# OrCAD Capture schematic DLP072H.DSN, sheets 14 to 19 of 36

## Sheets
14 PAGE18- 2ND PMD POWER SUPPLIES: size A3
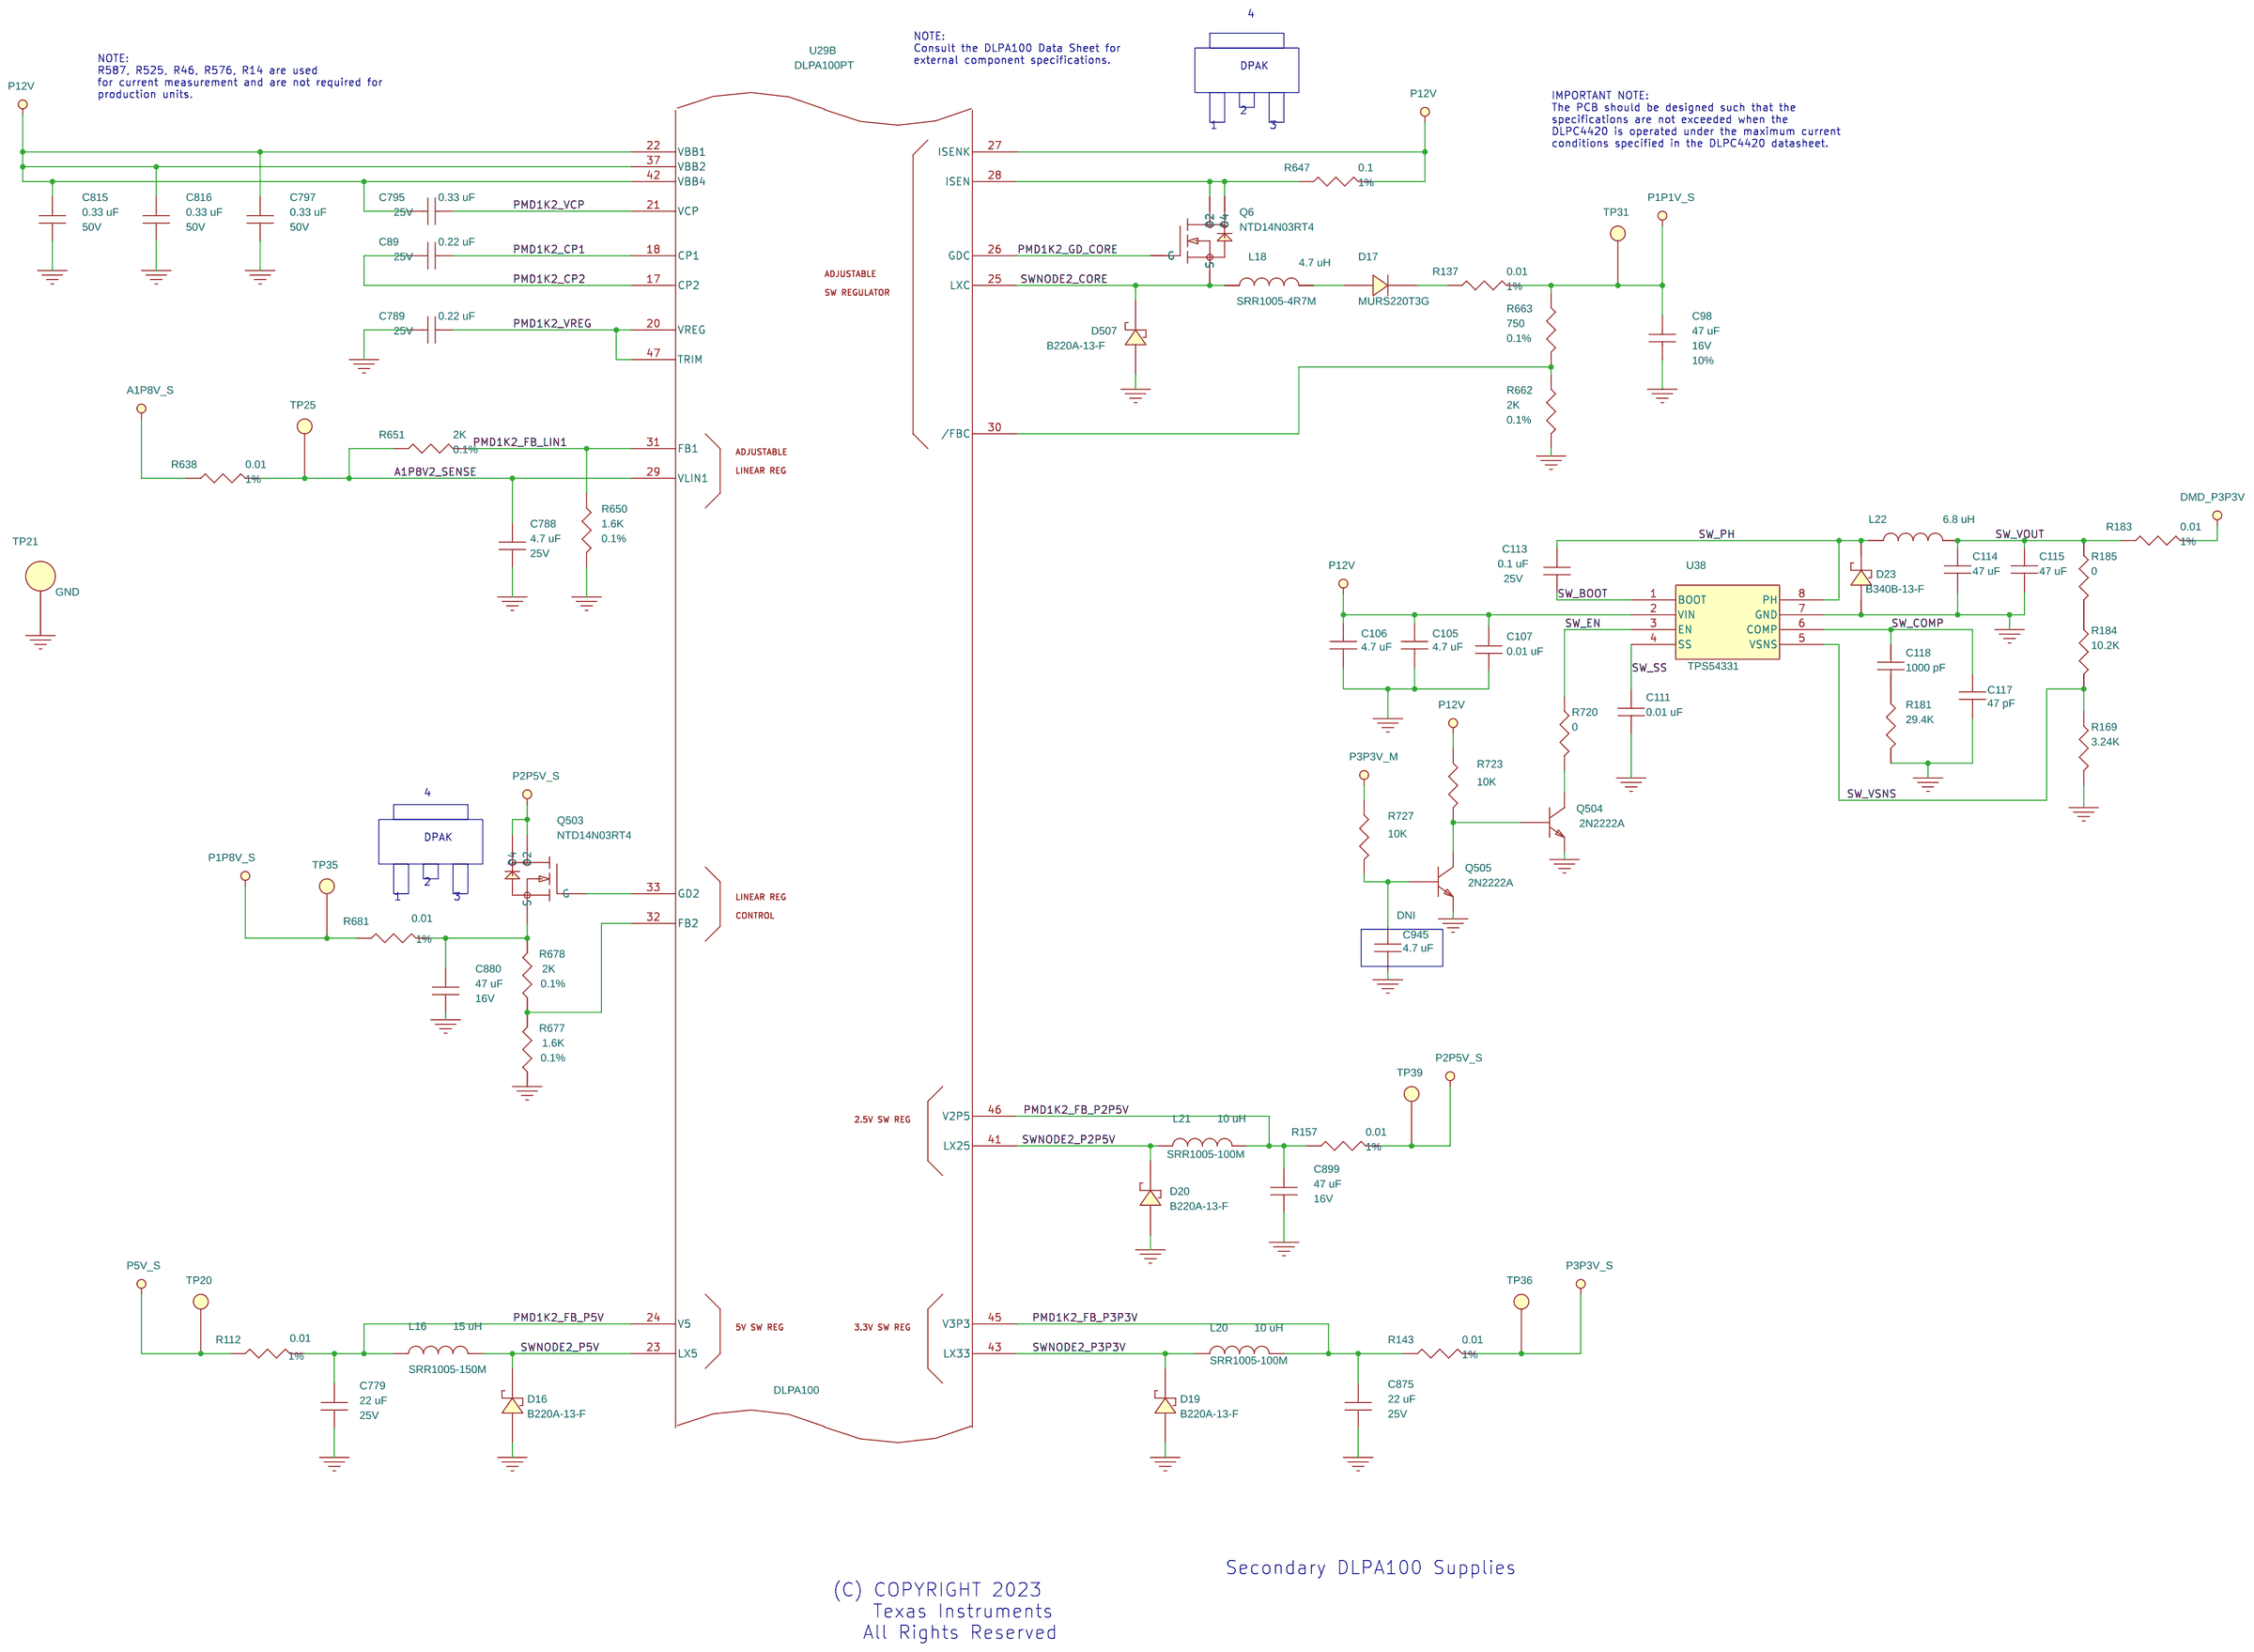
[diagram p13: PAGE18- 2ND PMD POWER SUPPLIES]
15 PAGE19 - COLOR WHEEL DRIVE: size A3
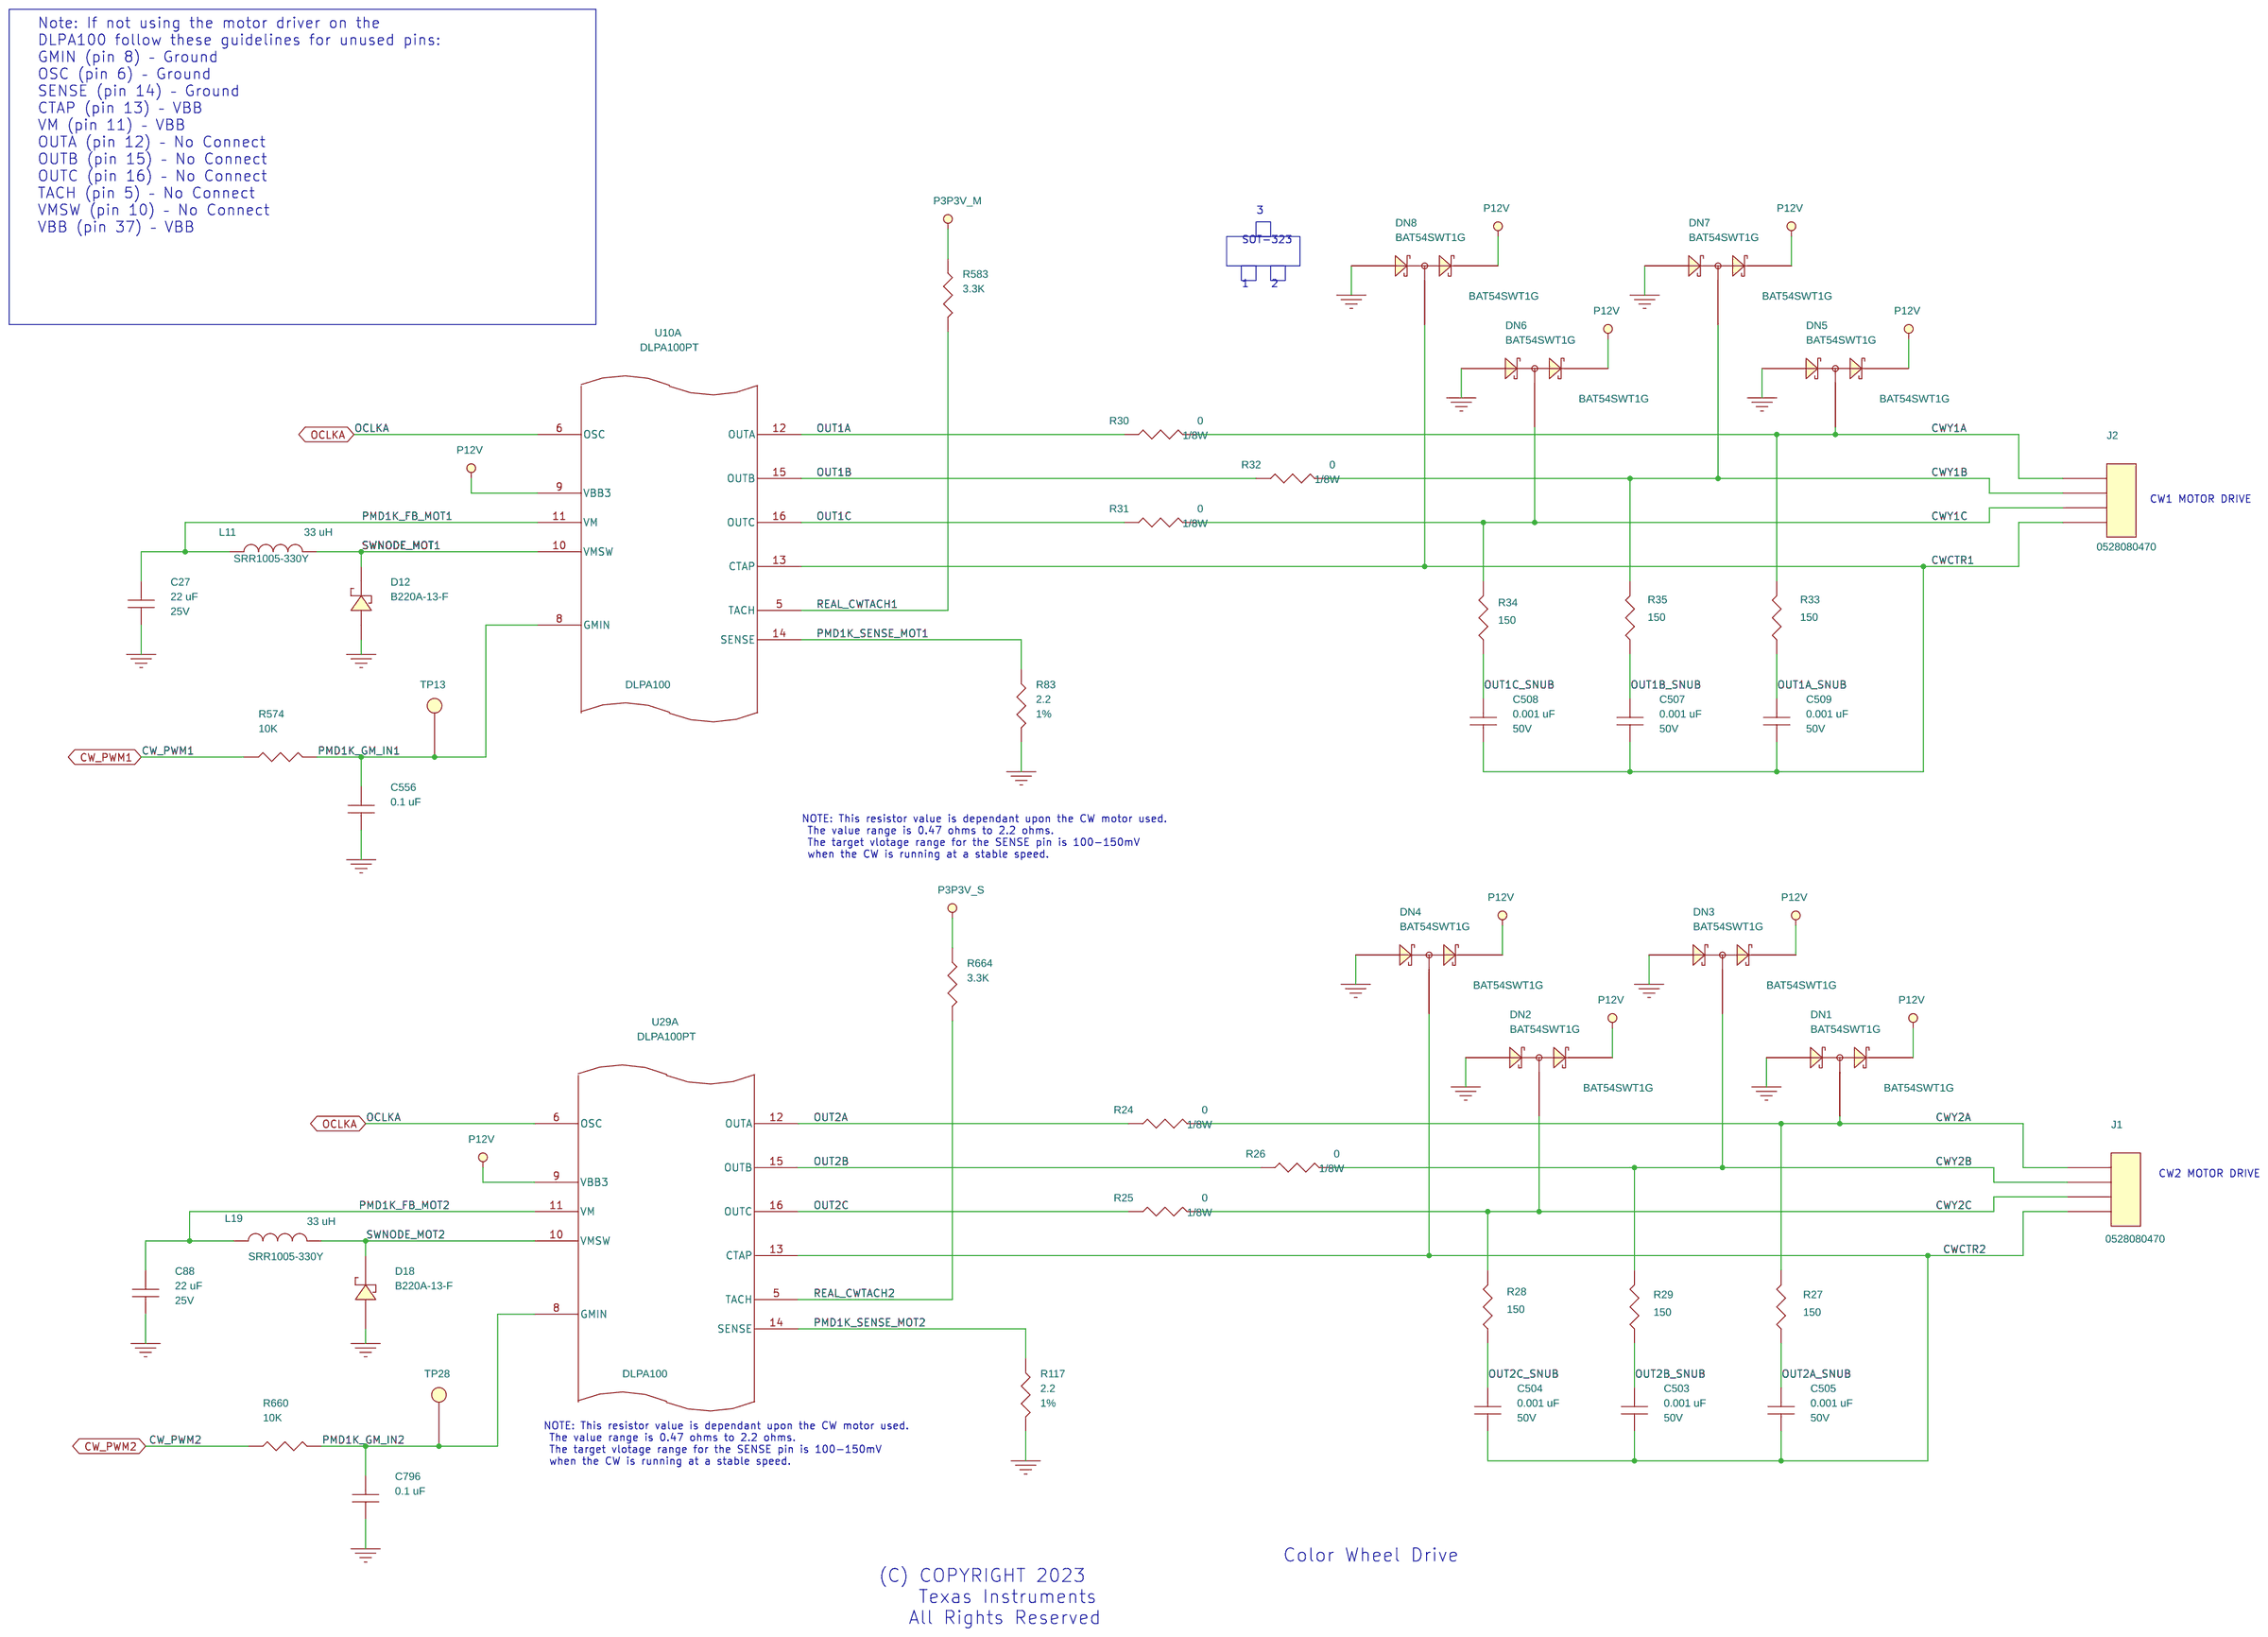
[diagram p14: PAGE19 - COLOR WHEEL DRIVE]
16 PAGE20 - FAN, CW INT & PERIPHLS: size A3
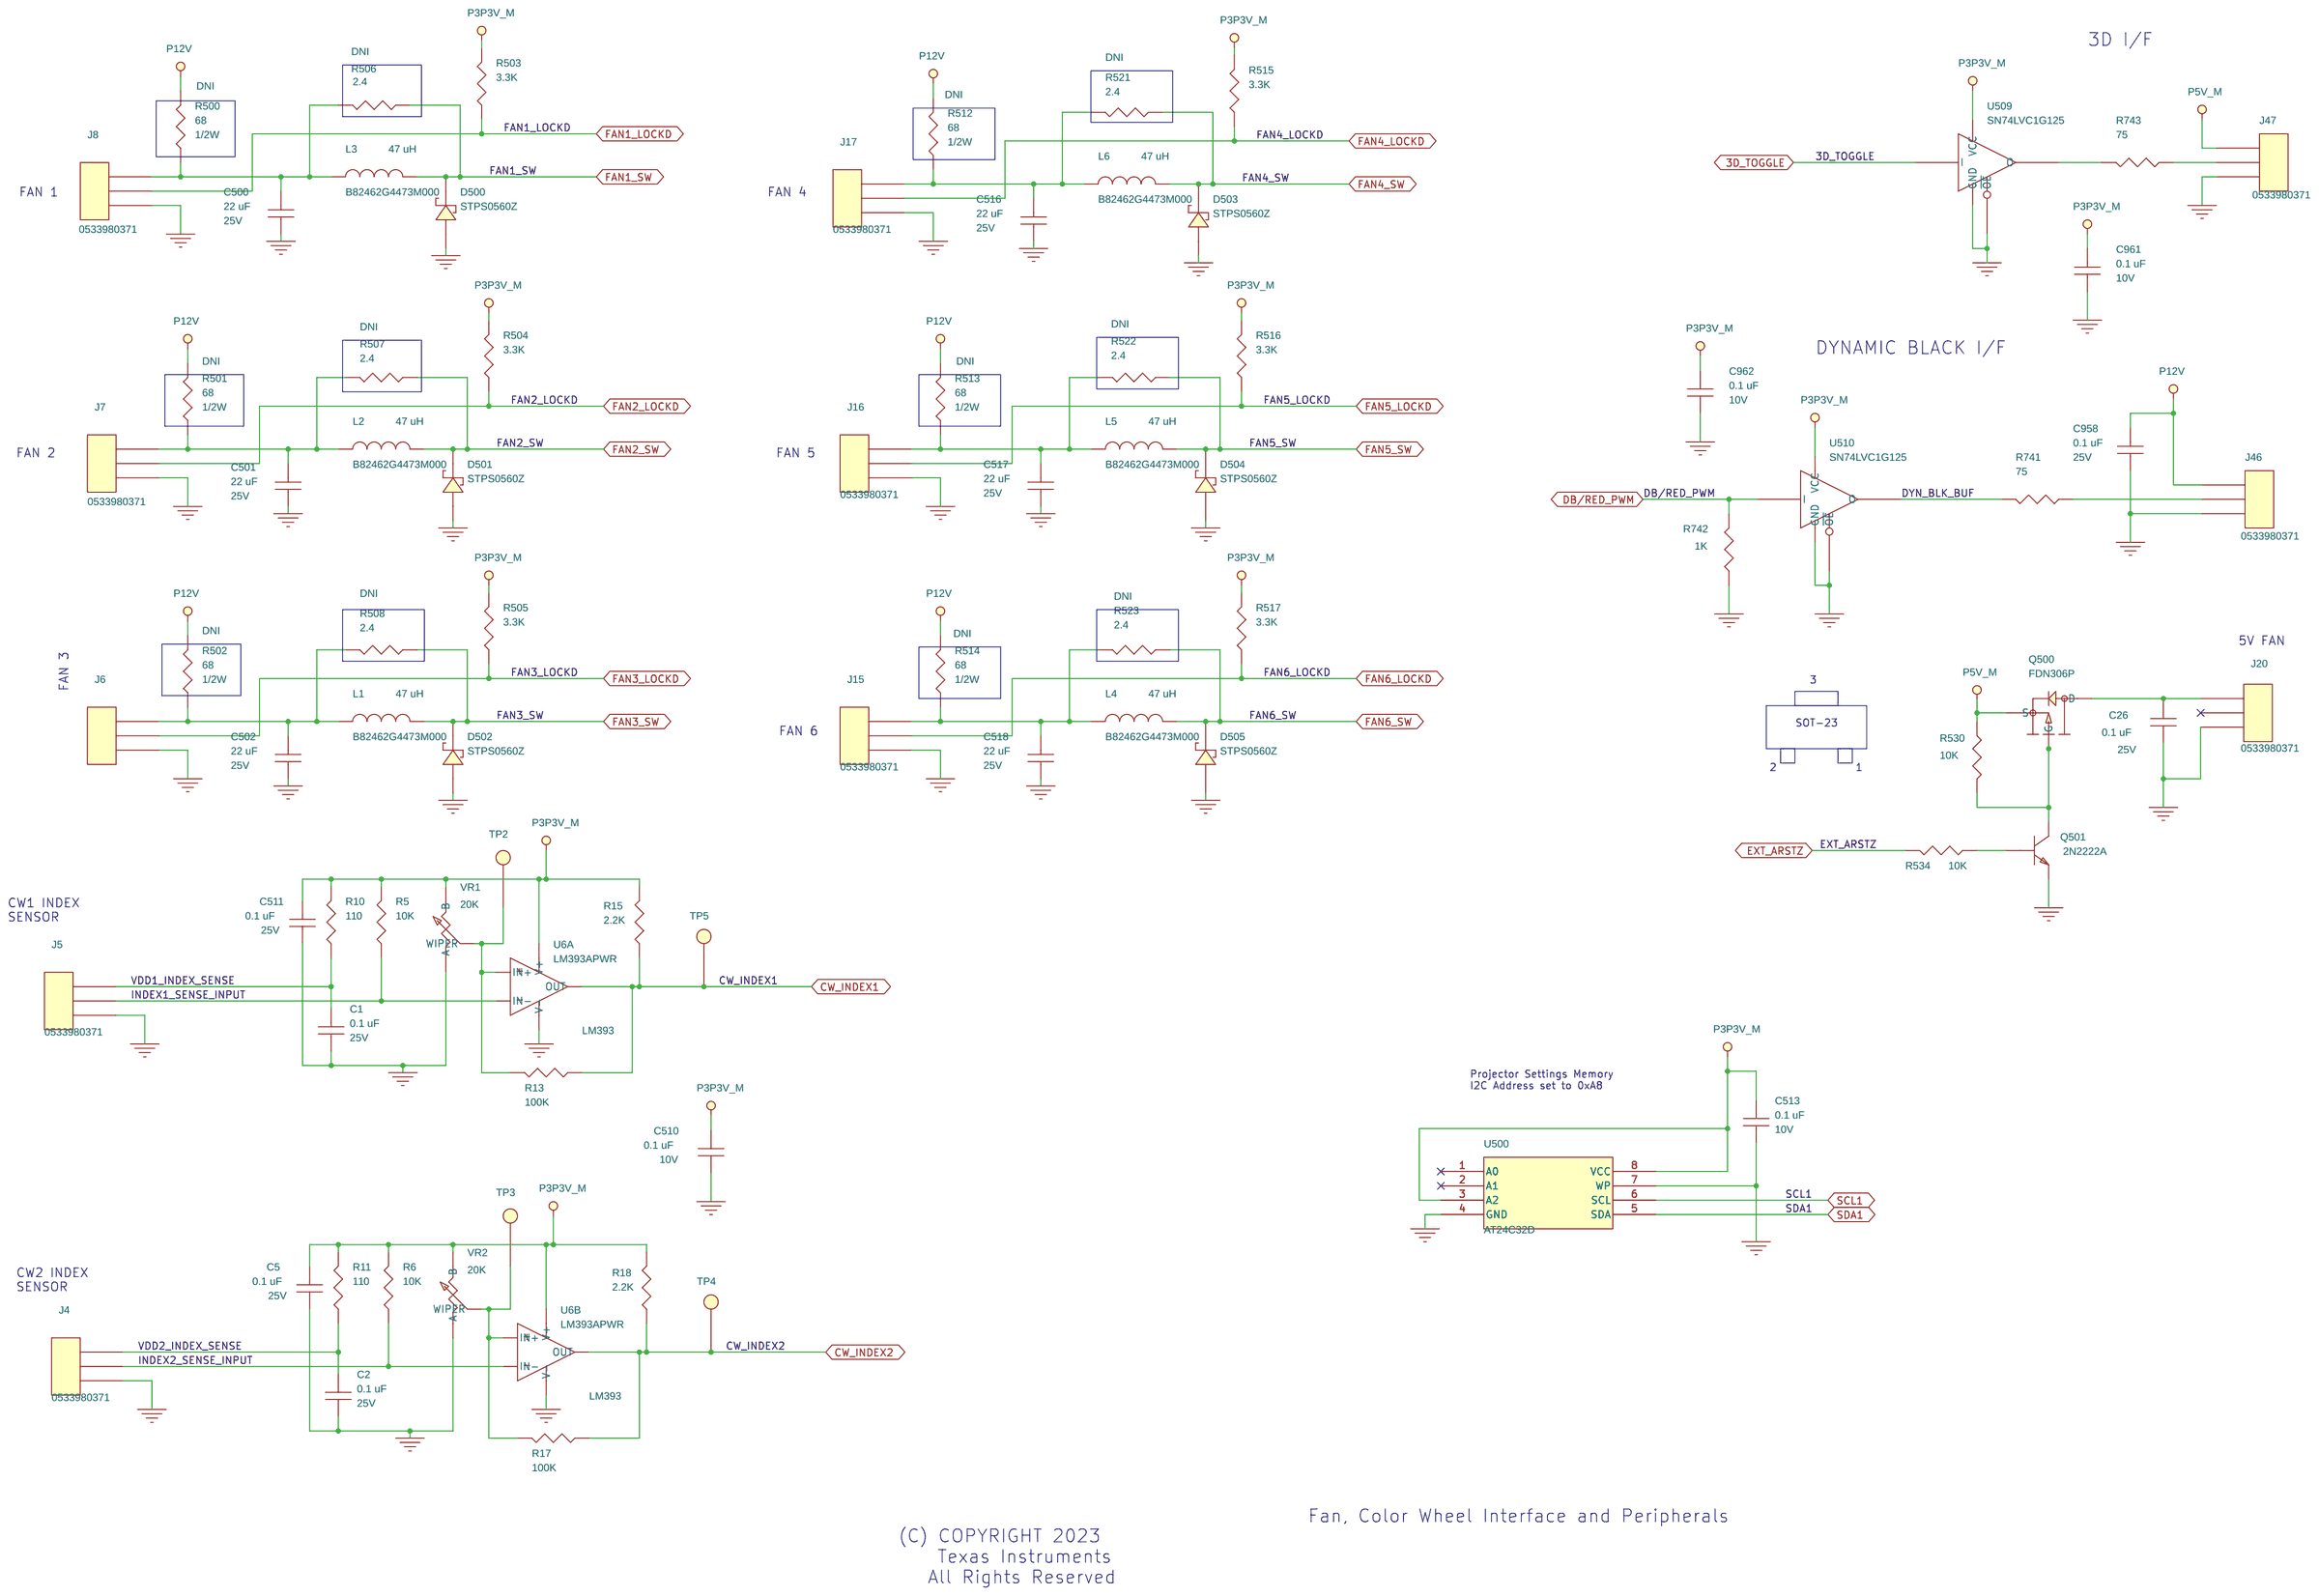
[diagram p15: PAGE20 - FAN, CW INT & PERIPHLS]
17 PAGE21 - GPIO, I2C, BALLAST: size A3
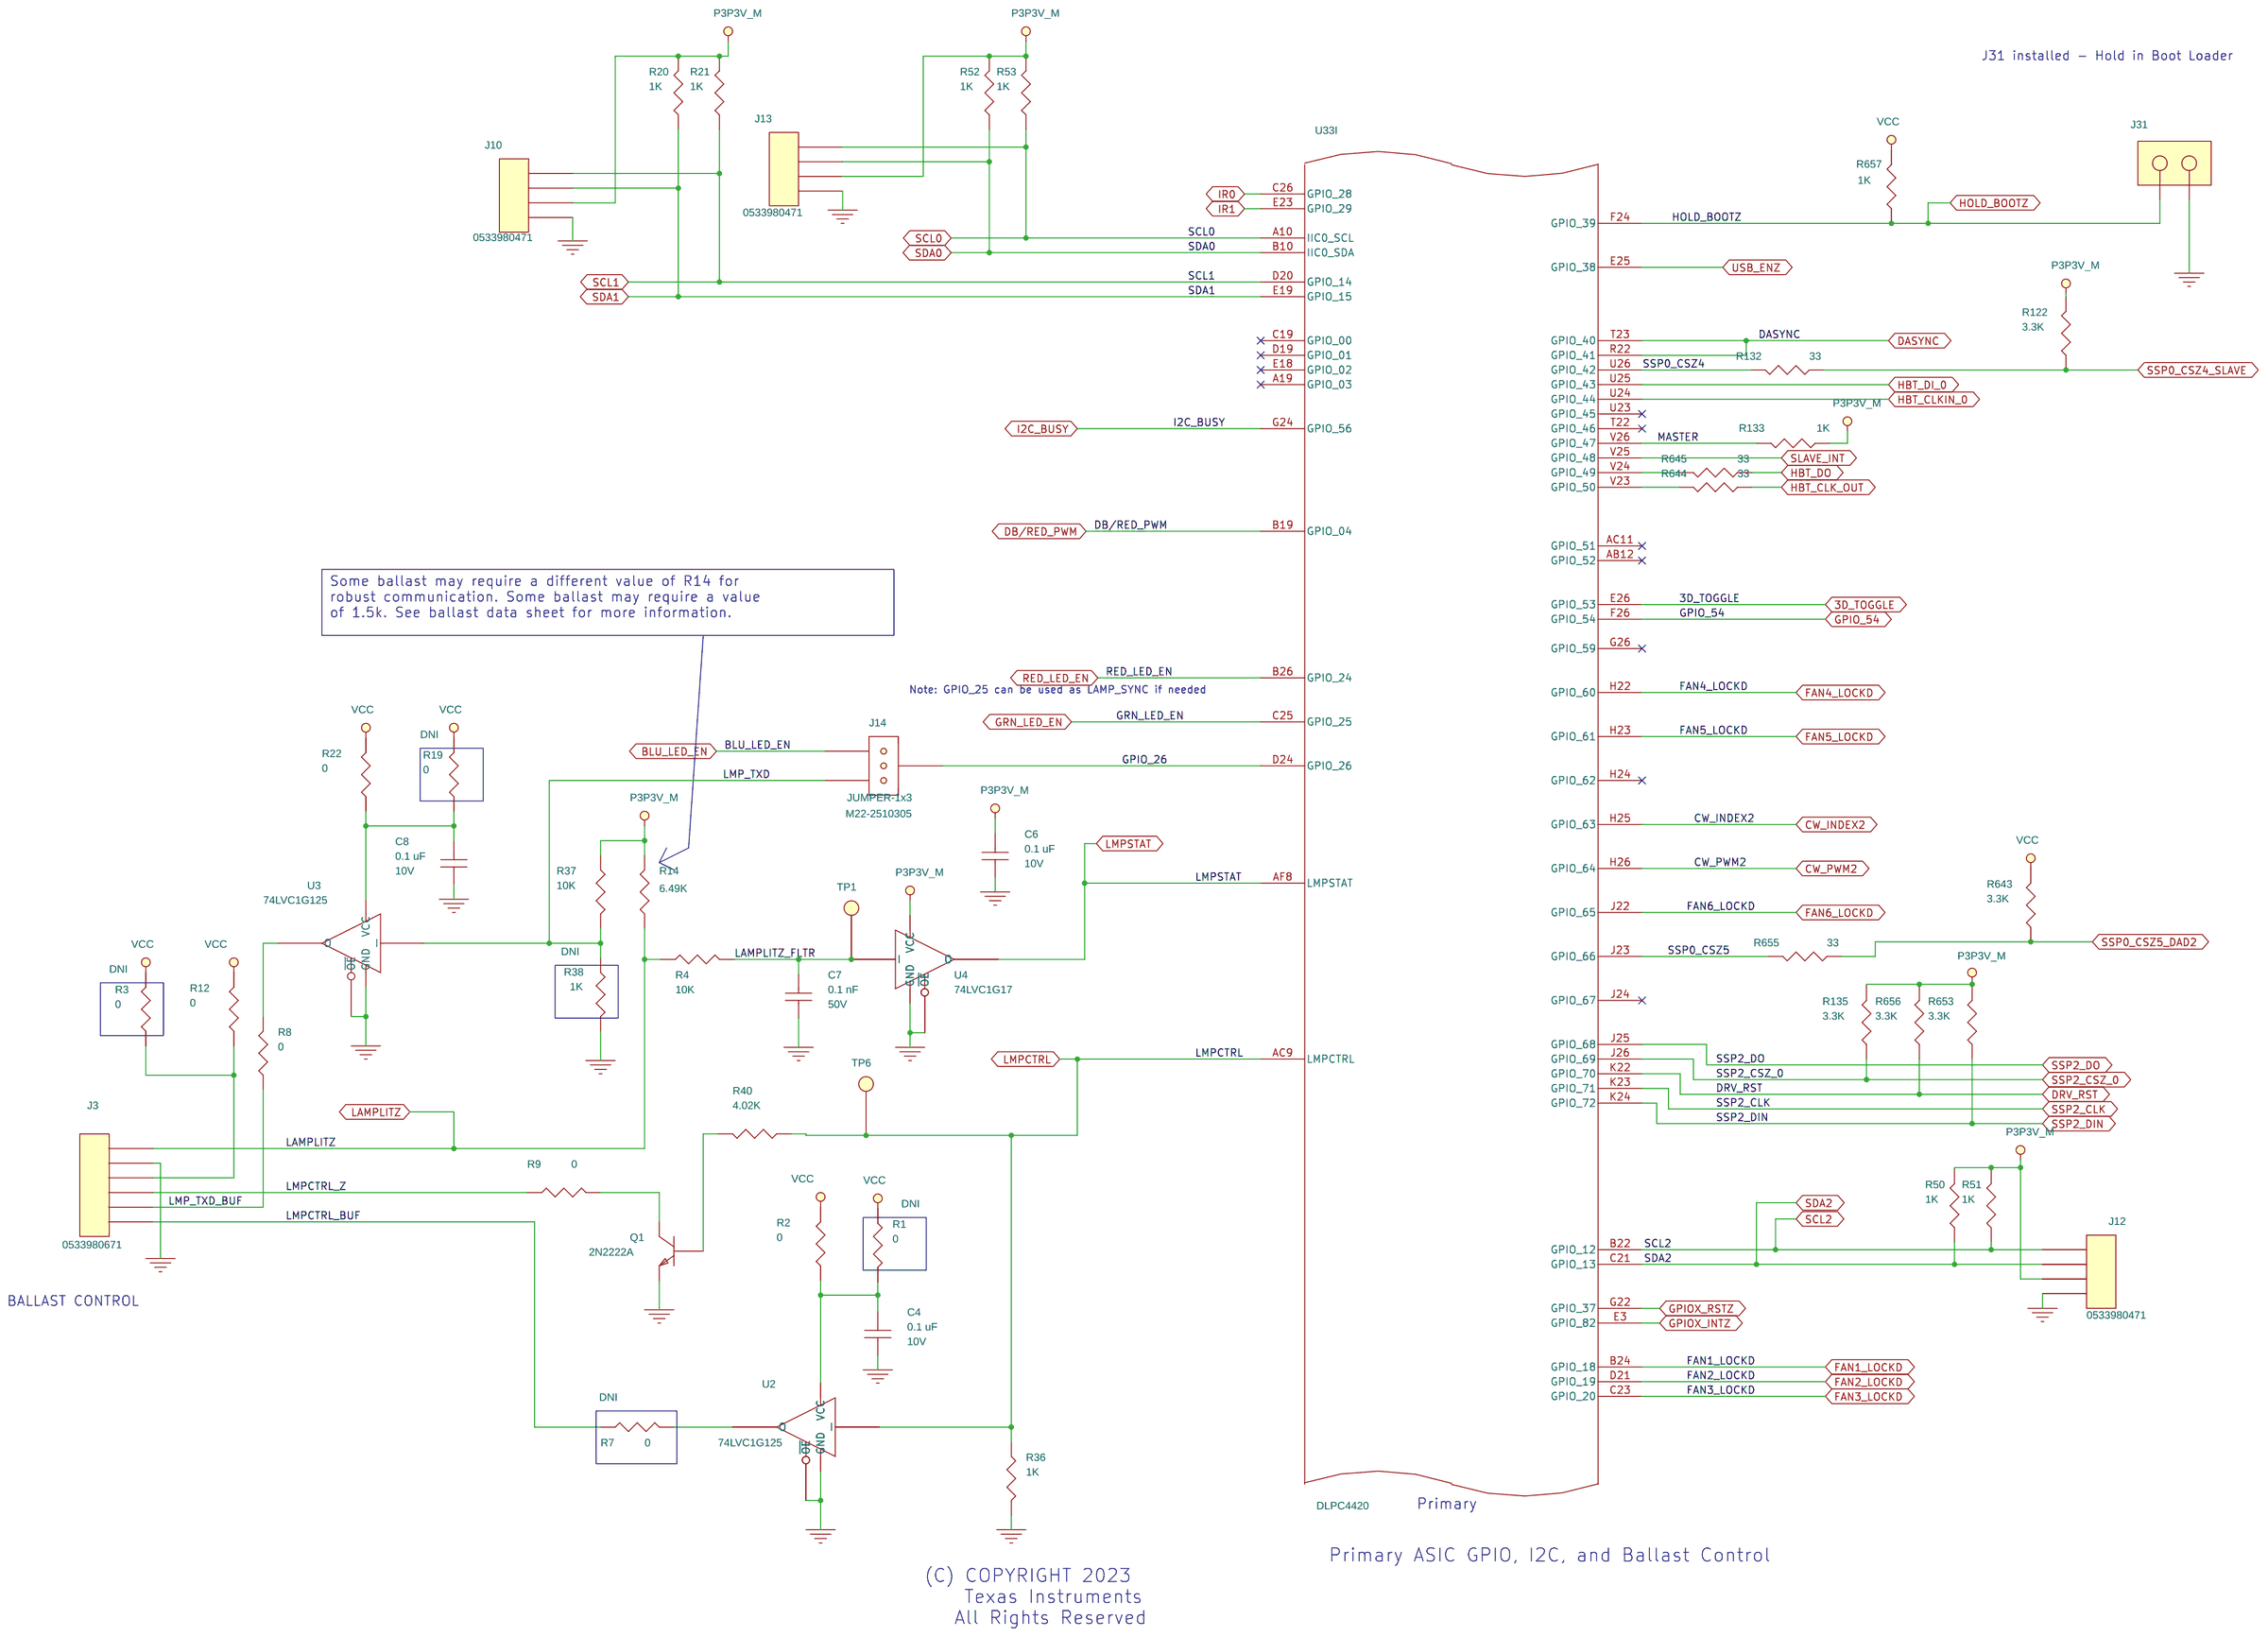
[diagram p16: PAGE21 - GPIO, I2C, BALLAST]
18 PAGE23 - TP, ARM JTAG, RESET: size Custom
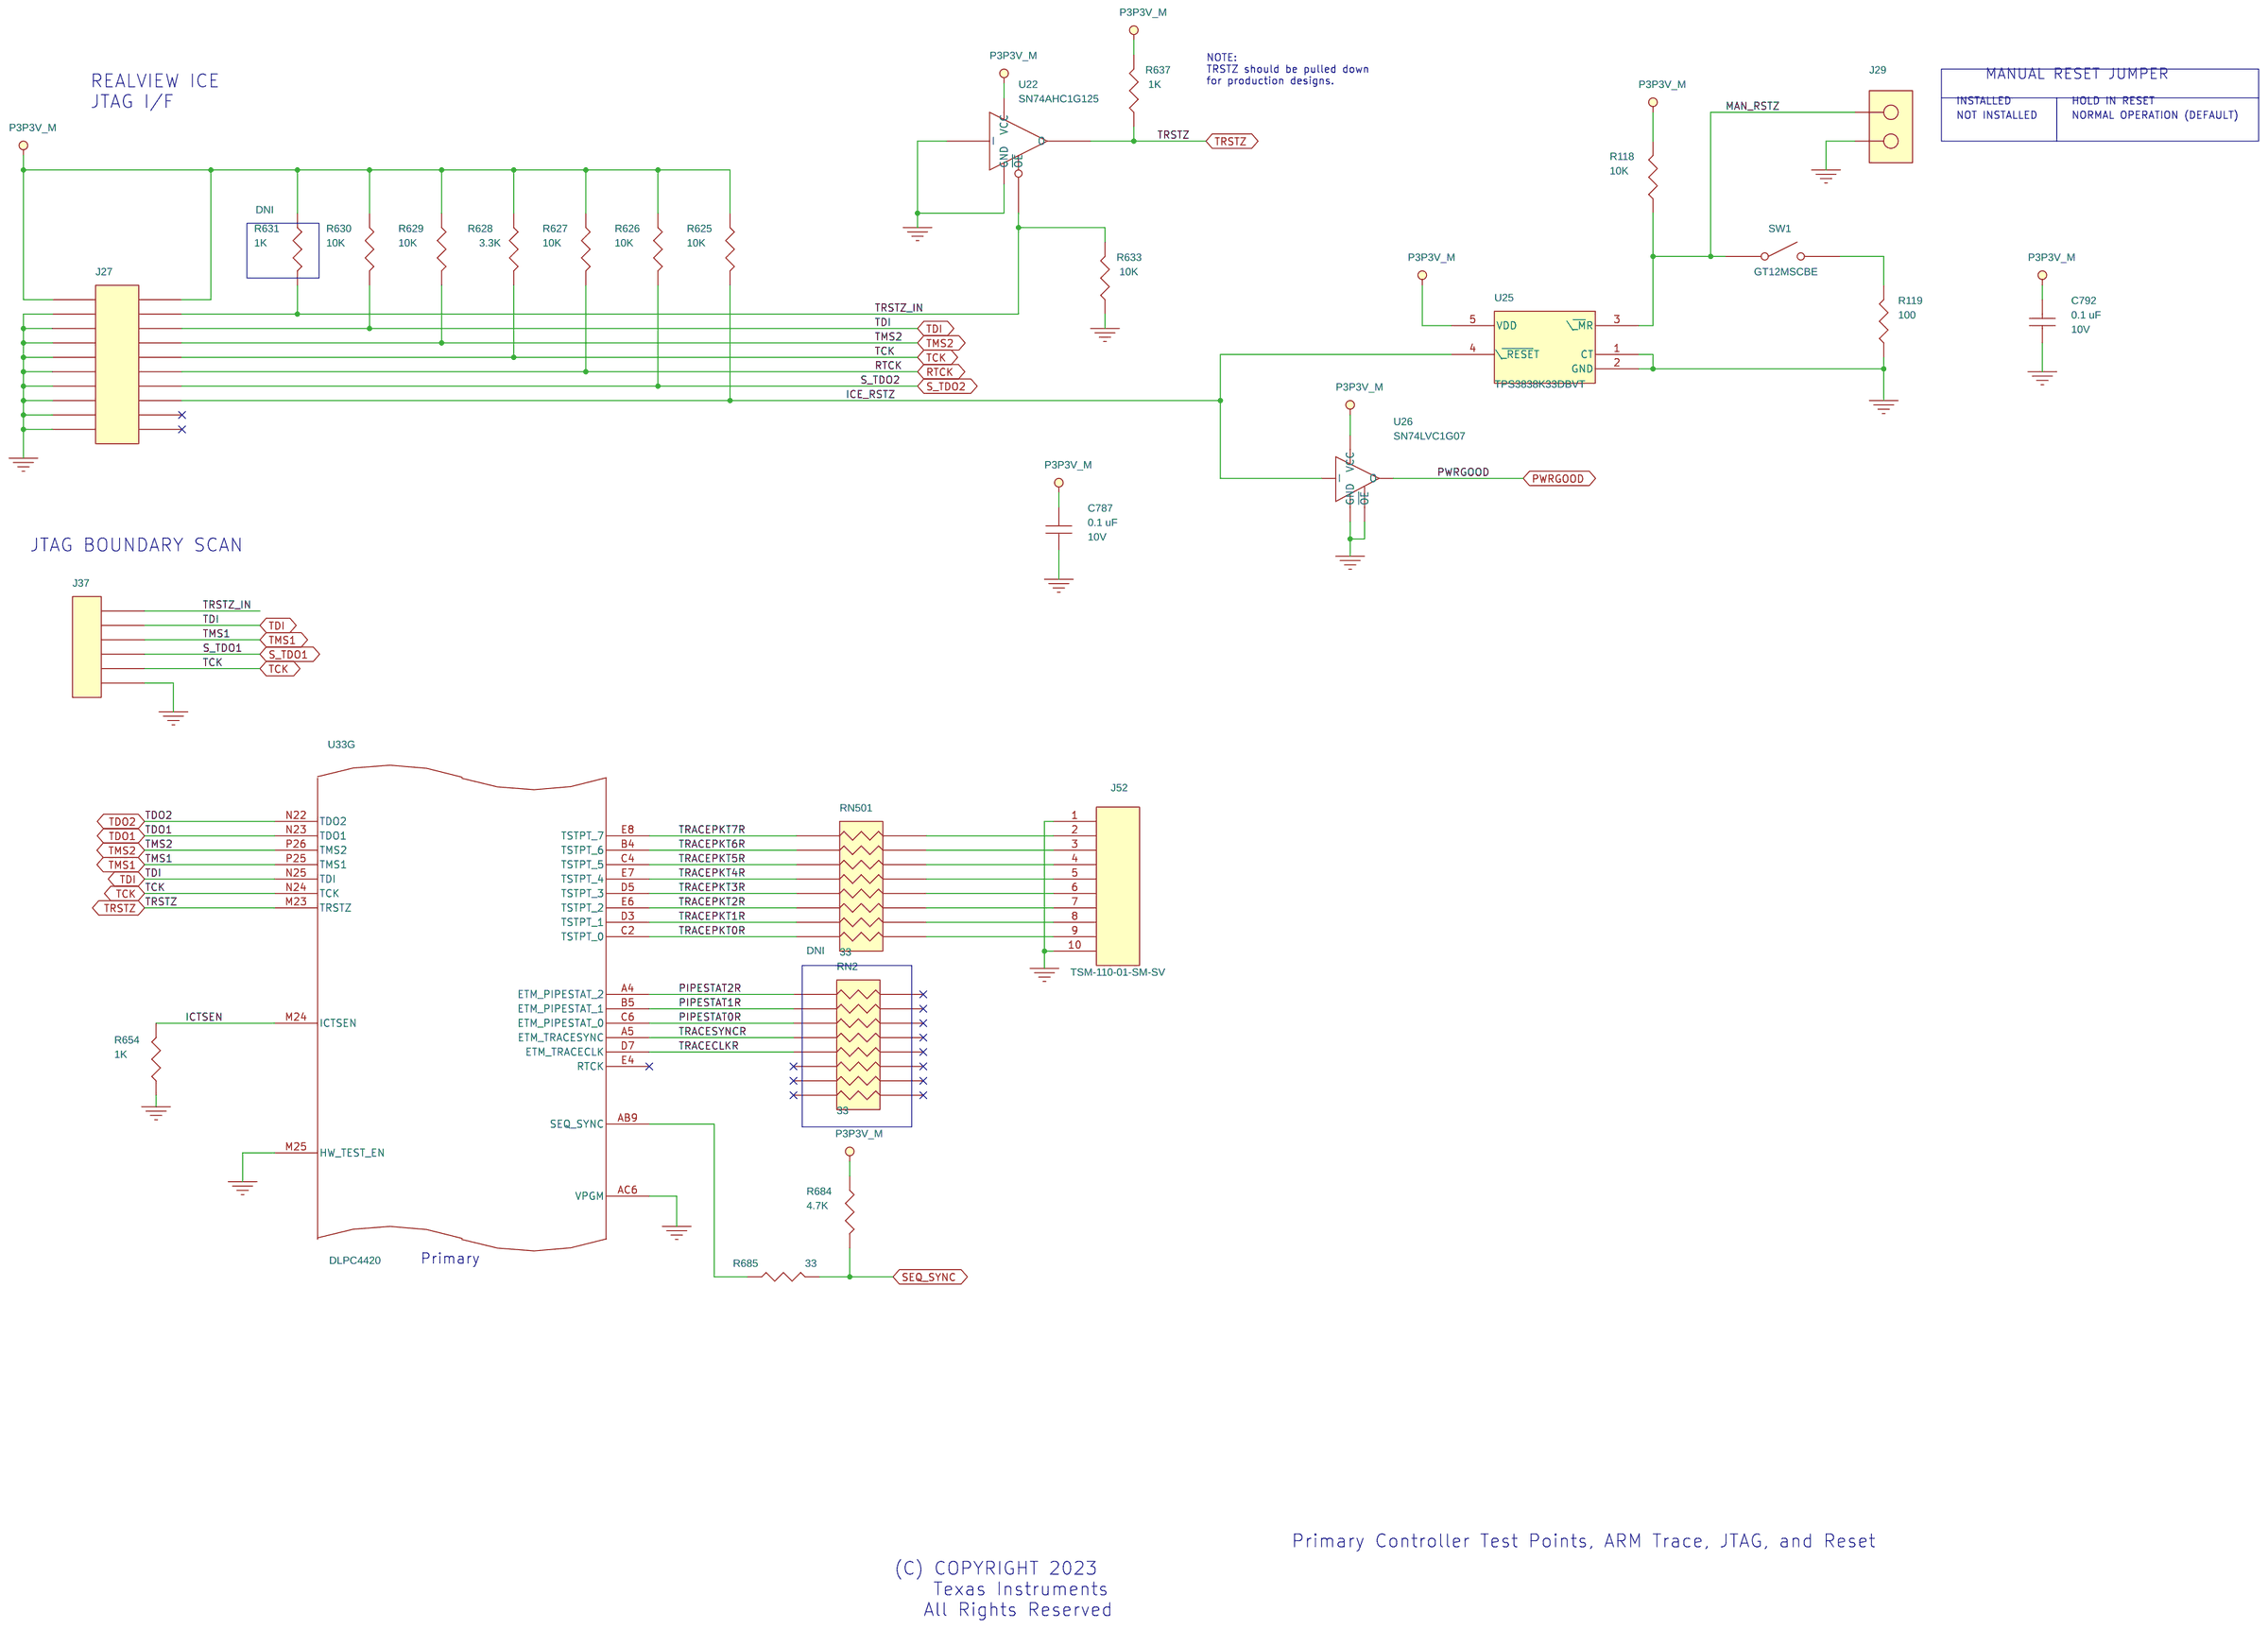
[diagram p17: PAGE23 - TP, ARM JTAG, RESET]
19 PAGE24 - SLAVE TP, ARM JTAG: size A3
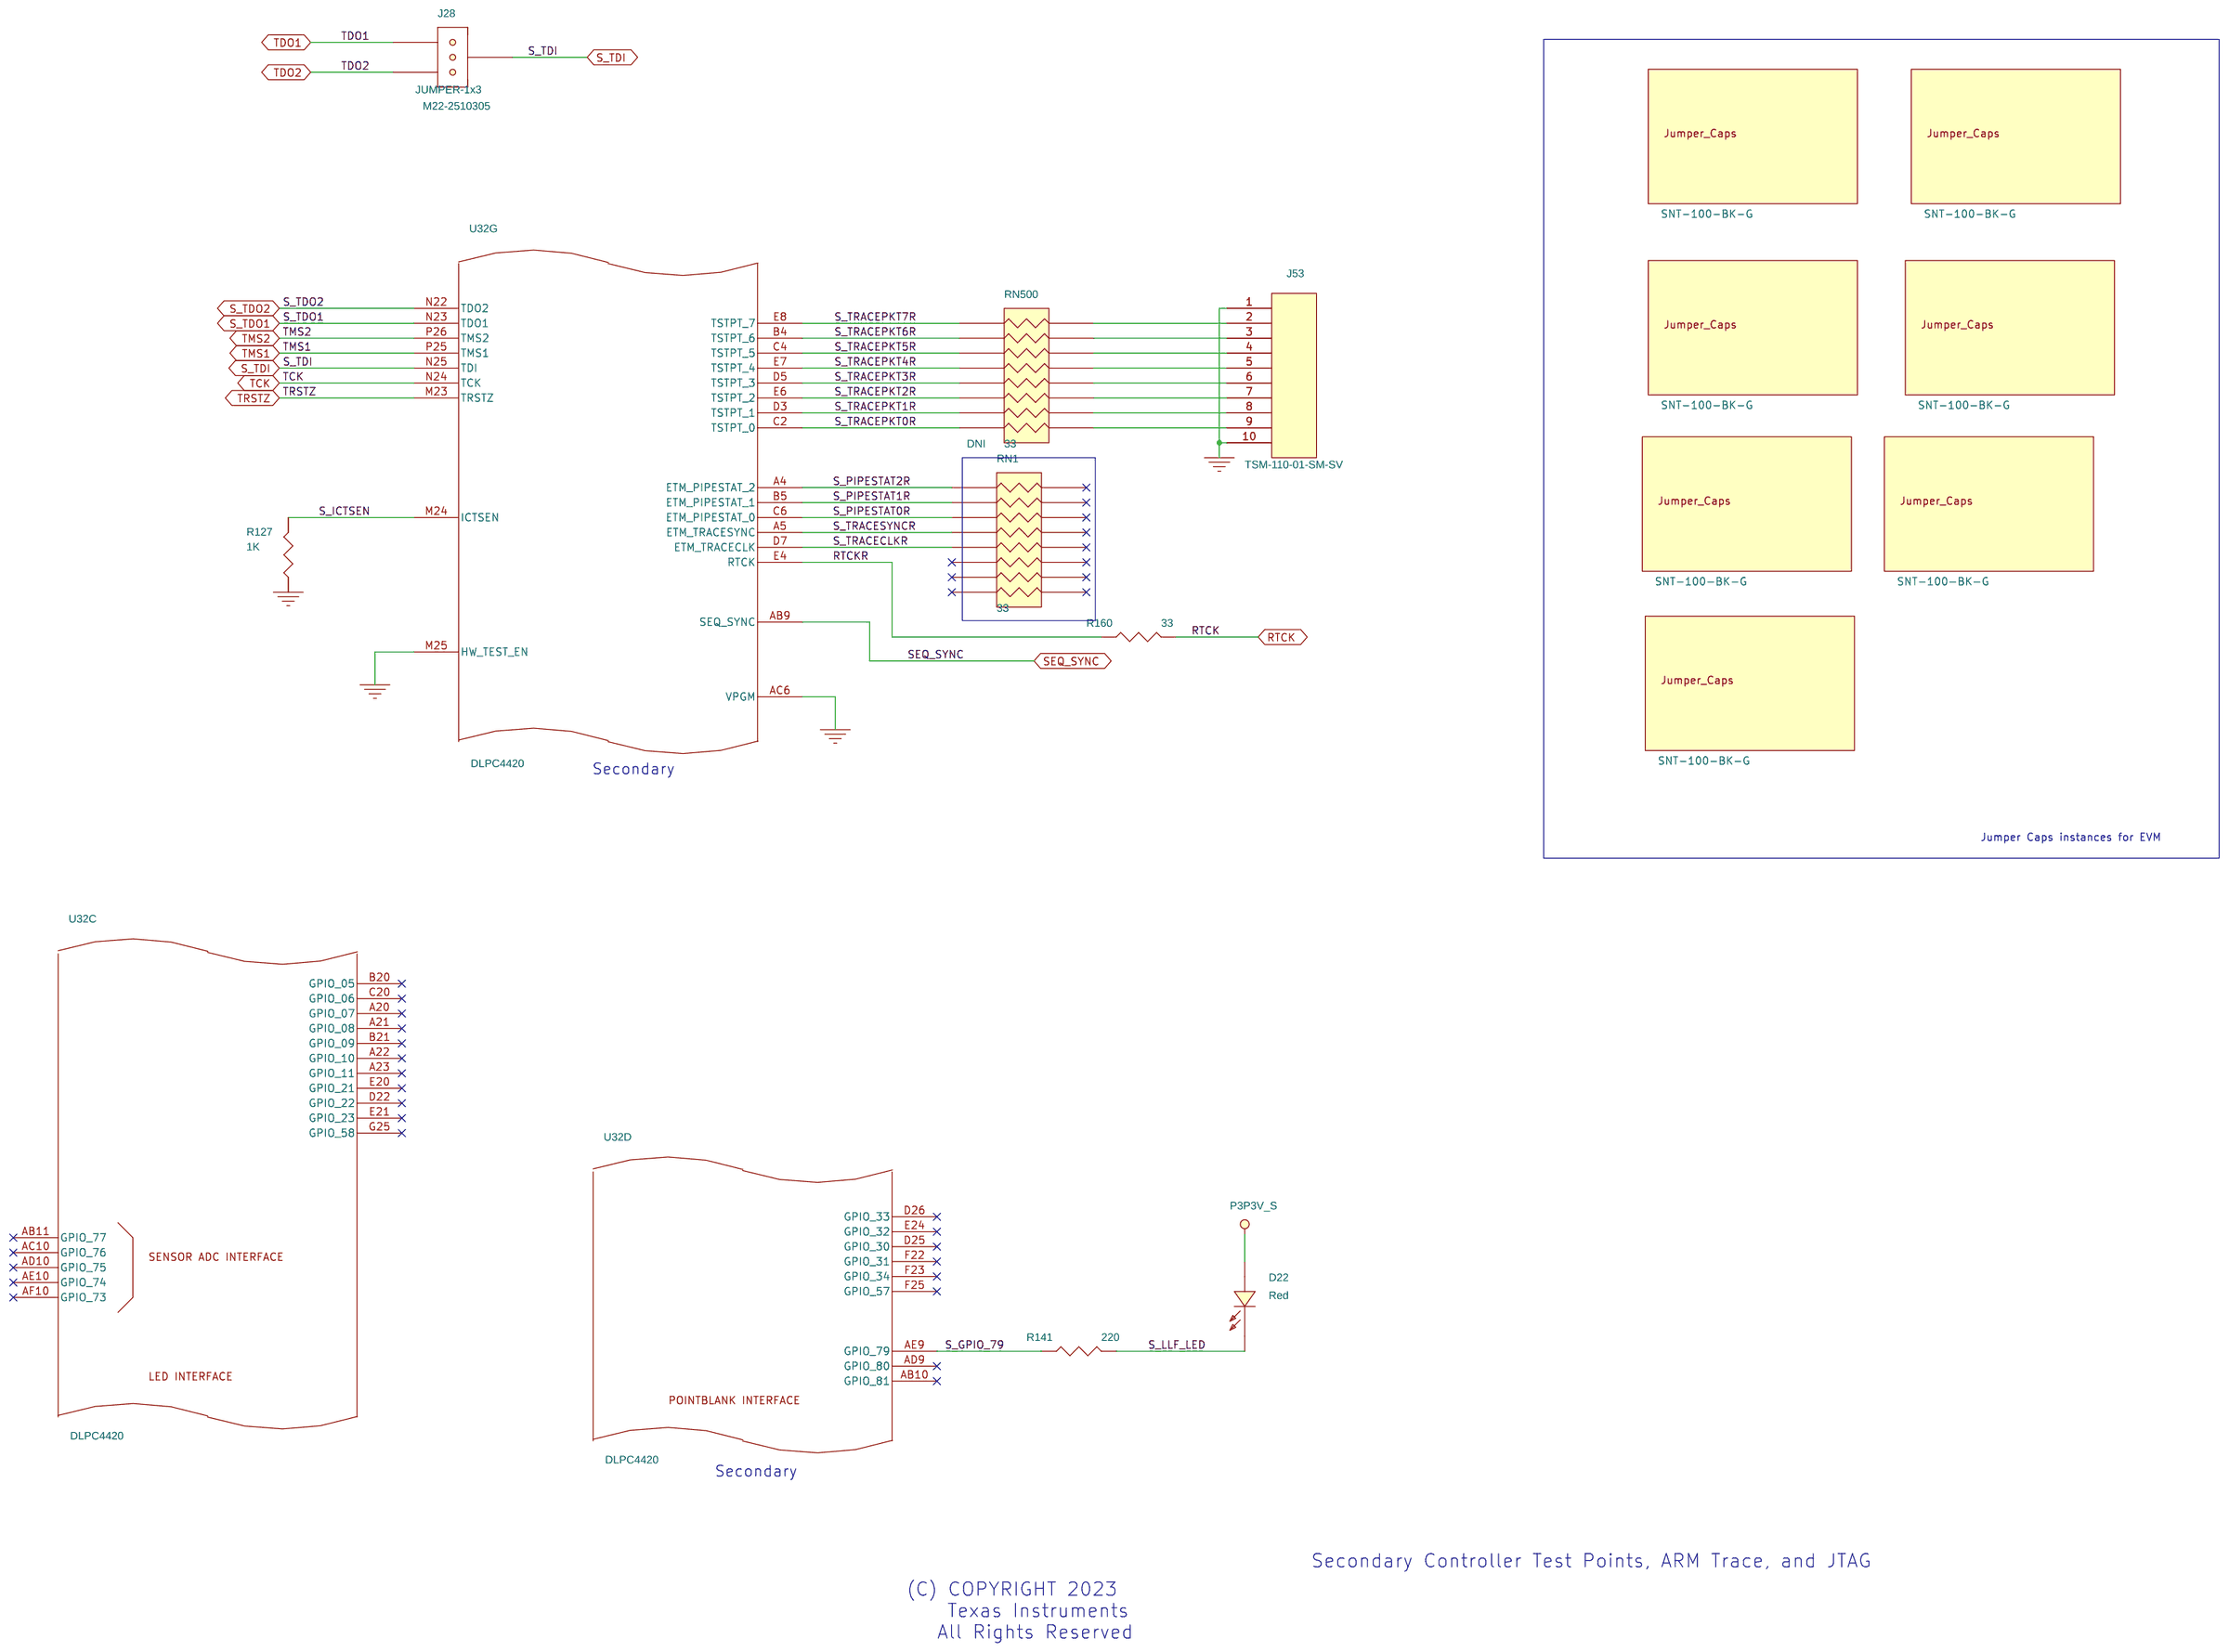
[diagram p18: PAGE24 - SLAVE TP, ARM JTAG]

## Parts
sheet PAGE16 - INPUT PWR & PMD1000
U10  DLPA100  [QF48_PPAD]  (sections A,B,C)
U29  DLPA100  [QF48_PPAD]  (sections A,B,C)
U32  DLPC4420  [BGA552-DDP4422_TI]  (sections A,B,C,D,E,F,G,H,I,J)
U33  DLPC4420  [BGA552-DDP4422_TI]  (sections A,B,C,D,E,F,G,H,I,J)
sheet PAGE18- 2ND PMD POWER SUPPLIES
C89  0.22 uF  [CAP_0805]
C98  47 uF  [CAP_1210]
C105  4.7 uF  [CAP_0805]
C106  4.7 uF  [CAP_0805]
C107  0.01 uF  [CAP_0603]
C111  0.01 uF  [CAP_0603]
C113  0.1 uF  [CAP_0603]
C114  47 uF  [CAP_1210]
C115  47 uF  [CAP_1210]
C117  47 pF  [CAP_0402]
C118  1000 pF  [CAP_0603]
C779  22 uF  [CAP_1210]
C788  4.7 uF  [CAP_0805]
C789  0.22 uF  [CAP_0805]
C795  0.33 uF  [CAP_0805]
C797  0.33 uF  [CAP_0805]
C815  0.33 uF  [CAP_0805]
C816  0.33 uF  [CAP_0805]
C875  22 uF  [CAP_1210]
C880  47 uF  [CAP_1210]
C899  47 uF  [CAP_1210]
C945  4.7 uF  [CAP_0805]
D16  B220A  [DIO-SMA]
D17  MURS220T3G  [DIO-SMB]
D19  B220A  [DIO-SMA]
D20  B220A  [DIO-SMA]
D23  B340B  [DIO-SMB]
D507  B220A  [DIO-SMA]
L16  15 uH  [IND_SRR1005]
L18  4.7 uH  [IND_SRR1005]
L20  10 uH  [IND_SRR1005]
L21  10 uH  [IND_SRR1005]
L22  6.8 uH  [IND2-SPR7030_BOU]
Q6  NTD14N03RT4  [SM_TO_252_DPAK]
Q503  NTD14N03RT4  [SM_TO_252_DPAK]
Q504  2N2222A  [SOT23AVXD]
Q505  2N2222A  [SOT23AVXD]
R112  0.01  [RES_0805]
R137  0.01  [RES_0805]
R143  0.01  [RES_0805]
R157  0.01  [RES_0805]
R169  3.24K  [RES_0402]
R181  29.4K  [RES_0402]
R183  0.01  [RES_0805]
R184  10.2K  [RES_0402]
R185  0  [RES_0402]
R638  0.01  [RES_0805]
R647  0.1  [RES_0805]
R650  1.6K  [RES_0402]
R651  2K  [RES_0402]
R662  2K  [RES_0402]
R663  750  [RES_0402]
R677  1.6K  [RES_0402]
R678  2K  [RES_0402]
R681  0.01  [RES_0805]
R720  0  [RES_0402]
R723  10K  [RES_0402]
R727  10K  [RES_0402]
TP20  Testpoint  [TP]
TP21  GND  [1p6mm_hole]
TP25  Testpoint  [TP]
TP31  Testpoint  [TP]
TP35  Testpoint  [TP]
TP36  Testpoint  [TP]
TP39  Testpoint  [TP]
U38  TPS54331  [SOIC8-D_TI]
sheet PAGE19 - COLOR WHEEL DRIVE
C27  22 uF  [CAP_1210]
C88  22 uF  [CAP_1210]
C503  0.001 uF  [CAP_0805]
C504  0.001 uF  [CAP_0805]
C505  0.001 uF  [CAP_0805]
C507  0.001 uF  [CAP_0805]
C508  0.001 uF  [CAP_0805]
C509  0.001 uF  [CAP_0805]
C556  0.1 uF  [CAP_0402]
C796  0.1 uF  [CAP_0402]
D12  B220A  [DIO-SMA]
D18  B220A  [DIO-SMA]
DN1  BAT54SWT1G  [SOT_323]
DN2  BAT54SWT1G  [SOT_323]
DN3  BAT54SWT1G  [SOT_323]
DN4  BAT54SWT1G  [SOT_323]
DN5  BAT54SWT1G  [SOT_323]
DN6  BAT54SWT1G  [SOT_323]
DN7  BAT54SWT1G  [SOT_323]
DN8  BAT54SWT1G  [SOT_323]
J1  CON4  [CONN4-52808_MOLEX]
J2  CON4  [CONN4-52808_MOLEX]
L11  33 uH  [IND_SRR1005]
L19  33 uH  [IND_SRR1005]
R24  0  [RES_0805]
R25  0  [RES_0805]
R26  0  [RES_0805]
R27  150  [RES_1206]
R28  150  [RES_1206]
R29  150  [RES_1206]
R30  0  [RES_0805]
R31  0  [RES_0805]
R32  0  [RES_0805]
R33  150  [RES_1206]
R34  150  [RES_1206]
R35  150  [RES_1206]
R83  2.2  [RES_1206]
R117  2.2  [RES_1206]
R574  10K  [RES_0402]
R583  3.3K  [RES_0402]
R660  10K  [RES_0402]
R664  3.3K  [RES_0402]
TP13  Testpoint  [TP]
TP28  Testpoint  [TP]
sheet PAGE20 - FAN, CW INT & PERIPHLS
C1  0.1 uF  [CAP_0603]
C2  0.1 uF  [CAP_0603]
C5  0.1 uF  [CAP_0603]
C26  0.1 uF  [CAP_0603]
C500  22 uF  [CAP_1210]
C501  22 uF  [CAP_1210]
C502  22 uF  [CAP_1210]
C510  0.1 uF  [CAP_0402]
C511  0.1 uF  [CAP_0603]
C513  0.1 uF  [CAP_0402]
C516  22 uF  [CAP_1210]
C517  22 uF  [CAP_1210]
C518  22 uF  [CAP_1210]
C958  0.1 uF  [CAP_0603]
C961  0.1 uF  [CAP_0402]
C962  0.1 uF  [CAP_0402]
D500  STPS0560Z  [SOD-123]
D501  STPS0560Z  [SOD-123]
D502  STPS0560Z  [SOD-123]
D503  STPS0560Z  [SOD-123]
D504  STPS0560Z  [SOD-123]
D505  STPS0560Z  [SOD-123]
J4  CON3  [CN3_53398_MOLEX]
J5  CON3  [CN3_53398_MOLEX]
J6  CON3  [CN3_53398_MOLEX]
J7  CON3  [CN3_53398_MOLEX]
J8  CON3  [CN3_53398_MOLEX]
J15  CON3  [CN3_53398_MOLEX]
J16  CON3  [CN3_53398_MOLEX]
J17  CON3  [CN3_53398_MOLEX]
J20  CON3  [CN3_53398_MOLEX]
J46  CON3  [CN3_53398_MOLEX]
J47  CON3  [CN3_53398_MOLEX]
L1  47 uH  [IND_SERH]
L2  47 uH  [IND_SERH]
L3  47 uH  [IND_SERH]
L4  47 uH  [IND_SERH]
L5  47 uH  [IND_SERH]
L6  47 uH  [IND_SERH]
Q500  FDN306P  [SOT23-3_FC]
Q501  2N2222A  [SOT23AVXD]
R5  10K  [RES_0402]
R6  10K  [RES_0402]
R10  110  [RES_0805]
R11  110  [RES_0805]
R13  100K  [RES_0402]
R15  2.2K  [RES_0603]
R17  100K  [RES_0402]
R18  2.2K  [RES_0603]
R500  68  [RES_1210]
R501  68  [RES_1210]
R502  68  [RES_1210]
R503  3.3K  [RES_0402]
R504  3.3K  [RES_0402]
R505  3.3K  [RES_0402]
R506  2.4  [RES_1210]
R507  2.4  [RES_1210]
R508  2.4  [RES_1210]
R512  68  [RES_1210]
R513  68  [RES_1210]
R514  68  [RES_1210]
R515  3.3K  [RES_0402]
R516  3.3K  [RES_0402]
R517  3.3K  [RES_0402]
R521  2.4  [RES_1210]
R522  2.4  [RES_1210]
R523  2.4  [RES_1210]
R530  10K  [RES_0402]
R534  10K  [RES_0402]
R741  75  [RES_0603]
R742  1K  [RES_0402]
R743  75  [RES_0603]
TP2  Testpoint  [TP]
TP3  Testpoint  [TP]
TP4  Testpoint  [TP]
TP5  Testpoint  [TP]
U6  LM393  [SOIC8-PW_TI]  (sections A,B)
U500  AT24C32D  [TSSOP_8]
U509  SN74LVC1G125  [SOT23-DBV_TI]
U510  SN74LVC1G125  [SOT23-DBV_TI]
VR1  20K  [POT-3314G]
VR2  20K  [POT-3314G]
sheet PAGE21 - GPIO, I2C, BALLAST
C4  0.1 uF  [CAP_0402]
C6  0.1 uF  [CAP_0402]
C7  0.1 nF  [CAP_0603]
C8  0.1 uF  [CAP_0402]
J3  CON6  [CONN6-53398-0690_MOLEX]
J10  CONN_4  [CONN4-53398_MOLEX]
J12  CONN_4  [CONN4-53398_MOLEX]
J13  CONN_4  [CONN4-53398_MOLEX]
J14  JUMPER-1x3  [HDR1X3-TMM1030X-X-S_SAM]
J31  HDR_2  [HDR2_2MM]
Q1  2N2222A  [SOT23AVXD]
R1  0  [RES_0402]
R2  0  [RES_0402]
R3  0  [RES_0402]
R4  10K  [RES_0402]
R7  0  [RES_0402]
R8  0  [RES_0402]
R9  0  [RES_0402]
R12  0  [RES_0402]
R14  6.49K  [RES_0402]
R19  0  [RES_0402]
R20  1K  [RES_0402]
R21  1K  [RES_0402]
R22  0  [RES_0402]
R36  1K  [RES_0402]
R37  10K  [RES_0402]
R38  1K  [RES_0402]
R40  4.02K  [RES_0603]
R50  1K  [RES_0402]
R51  1K  [RES_0402]
R52  1K  [RES_0402]
R53  1K  [RES_0402]
R122  3.3K  [RES_0402]
R132  33  [RES_0402]
R133  1K  [RES_0402]
R135  3.3K  [RES_0402]
R643  3.3K  [RES_0402]
R644  33  [RES_0402]
R645  33  [RES_0402]
R653  3.3K  [RES_0402]
R655  33  [RES_0402]
R656  3.3K  [RES_0402]
R657  1K  [RES_0402]
TP1  Testpoint  [TP]
TP6  Testpoint  [TP]
U2  74LVC1G125  [SOT23-DBV_TI]
U3  74LVC1G125  [SOT23-DBV_TI]
U4  74LVC1G17  [SOT23-DBV_TI]
sheet PAGE23 - TP, ARM JTAG, RESET
C787  0.1 uF  [CAP_0402]
C792  0.1 uF  [CAP_0402]
J27  CON20A  [HDR10X2-5103308_TYCO]
J29  HDR_2  [HDR2_2MM]
J37  CON6  [CONN6-53398-0690_MOLEX]
J52  TSM-110-01-SM-SV  [CN-10-2_54MM]
R118  10K  [RES_0402]
R119  100  [RES_0402]
R625  10K  [RES_0402]
R626  10K  [RES_0402]
R627  10K  [RES_0402]
R628  3.3K  [RES_0402]
R629  10K  [RES_0402]
R630  10K  [RES_0402]
R631  1K  [RES_0402]
R633  10K  [RES_0402]
R637  1K  [RES_0402]
R654  1K  [RES_0402]
R684  4.7K  [RES_0402]
R685  33  [RES_0402]
RN2  33  [RNET16-EXB-2HV_PAN]
RN501  33  [RNET16-EXB-2HV_PAN]
SW1  SW SPST  [SW_GT12]
U22  SN74AHC1G125  [SOT23-DBV_TI]
U25  TPS3838  [SOT23-DBV_TI]
U26  SN74LVC1G07  [SOT23-DBV_TI]
sheet PAGE24 - SLAVE TP, ARM JTAG
D22  Red  [D_0603]
J28  JUMPER-1x3  [HDR1X3-TMM1030X-X-S_SAM]
J53  TSM-110-01-SM-SV  [CN-10-2_54MM]
PCB2  SNT-100-BK-G
PCB3  SNT-100-BK-G
PCB4  SNT-100-BK-G
PCB5  SNT-100-BK-G
PCB6  SNT-100-BK-G
PCB7  SNT-100-BK-G
PCB8  SNT-100-BK-G
R127  1K  [RES_0402]
R141  220  [RES_0603]
R160  33  [RES_0402]
RN1  33  [RNET16-EXB-2HV_PAN]
RN500  33  [RNET16-EXB-2HV_PAN]

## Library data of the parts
U10 U29 = PMD1000_0: IC, Power and Motor Driver; CCA: 140; MFG: TI; Part Number: DLPA100PT; SOURCE: PROVIDED BY TI
U32 U33 = DDP442x: IC, ASIC; CCA: 54; MFG: TI; Part Number: DLPC4420ZPC; SOURCE: PROVIDED BY TI
C89 C789 = CAP_NP: Capacitor; CCA: 38; MFG: KEMET; Part Number: C0805C224K5RACTU; RATING: 25V; SOURCE: DIGI 399-3491-1-ND; TOLERANCE: 10%; Type: X7R
C98 C114 C115 C880 C899 = CAP_NP: Capacitor; CCA: 115; MFG: SAMSUNG; Part Number: CL32A476KOJNNNE; RATING: 16V; SOURCE: DIGI 490-3887-1-ND; TOLERANCE: 10%; Type: X5R
C105 C106 C788 = CAP_NP: Capacitor; CCA: 42; MFG: TDK; Part Number: C2012X7R1E475K125AB; RATING: 25V; SOURCE: DIGI 445-5972-1-ND; TOLERANCE: 10%; Type: X7R
C107 C111 = CAP_NP: Capacitor; CCA: 47; MFG: YAGEO; Part Number: CC0603KRX7R8BB103; RATING: 25V; TOLERANCE: 10%; Type: X7R
C1 C2 C5 C26 C113 C511 C958 = CAP_NP: Capacitor; CCA: 48; MFG: KEMET; Part Number: C0603C104K3RACTU; RATING: 25V; SOURCE: DIGI PCC2277CT-ND; TOLERANCE: 10%; Type: X7R
C117 = CAP_NP: Capacitor; CCA: 121; MFG: YAGEO; Part Number: CC0402JRNPO9BN470; RATING: 50V; SOURCE: DIGI 490-1287-1-ND; TOLERANCE: 5%; Type: NP0
C118 = CAP_NP: Capacitor; CCA: 116; MFG: KEMET; Part Number: C0603C102K5RAC7867; RATING: 50V; SOURCE: DIGI 445-4924-4-ND; TOLERANCE: 10%; Type: X7R
C27 C88 C500-C502 C516-C518 C779 C875 = CAP_NP: Capacitor; CCA: 16; MFG: AVX; Part Number: 12103D226KAT2A; RATING: 25V; SOURCE: DIGI 490-1882-2-ND; TOLERANCE: 10%; Type: X5R
C795 = CAP_NP: Capacitor; CCA: 113; MFG: MURATA; Part Number: GRM21BR71E334KA01L; RATING: 25V; SOURCE: DIGI 490-1677-1-ND; TOLERANCE: 10%; Type: X7R
C797 C815 C816 = CAP_NP: Capacitor; CCA: 113; MFG: SAMSUNG; Part Number: CL21B334KBFNNNE; RATING: 50V; SOURCE: DIGI 490-1677-1-ND; TOLERANCE: 10%; Type: X7R
C945 = CAP_NP: Capacitor; CCA: 42; DNI: DNI; MFG: TDK; Part Number: C2012X7R1E475K; RATING: 25V; SOURCE: DIGI 445-5972-1-ND; TOLERANCE: 10%; Type: X7R
D12 D16 D18-D20 D507 = DIODE_SCHOTTKY: Diode, Schottky; CCA: 27; MFG: DIODES INC; Part Number: B220A-13-F; RATING: 20V, 2A; SOURCE: DIGI B220A-FDICT-ND
D17 = DIODE: Diode; CCA: 136; MFG: ON SEMI; RATING: 200V; SOURCE: DIGI MURS220T3GOSCT-ND
D23 = DIODE_SCHOTTKY: Diode, Schottky; CCA: 27; MFG: DIODES INC; Part Number: B340B-13-F; RATING: 40V, 3A; SOURCE: DIGIB340B-FDICT-ND
L16 = INDUCTOR: Inductor; CCA: 156; ICA_MFR_NAME: STEWARD; ICA_PARTNUM: $$731362$$MI0603J680R-10; MFG: BOURNS; Part Number: SRR1005-150M; RATING: 1.7A; SOURCE: DIGI SRR1005-150M-ND; TOLERANCE: 20%
L18 = INDUCTOR: Inductor; CCA: 154; ICA_MFR_NAME: STEWARD; ICA_PARTNUM: $$731362$$MI0603J680R-10; MFG: BOURNS; Part Number: SRR1005-4R7M; RATING: 2.5A; SOURCE: DIGI SRR1005-4R7M-ND; TOLERANCE: 20%
L20 L21 = INDUCTOR: Inductor; CCA: 155; ICA_MFR_NAME: STEWARD; ICA_PARTNUM: $$731362$$MI0603J680R-10; MFG: BOURNS; Part Number: SRR1005-100M; RATING: 2A; SOURCE: DIGI SRR1005-100M-ND; TOLERANCE: 20%
L22 = INDUCTOR: Inductor; CCA: 153; MFG: EATON; Part Number: HCMA0703-6R8-R; RATING: 4.5A; SOURCE: DIGI SRP7030-6R8FMCT-ND
Q6 Q503 = NTD14NO3RT4_0: MOSFET, N-Channel; CCA: 138; MFG: ON SEMI; Part Number: NTD14N03RT4G; RATING: 25Vdss, 14A; SOURCE: DIGI NTD14N03RT4OSCT-ND
Q1 Q501 Q504 Q505 = 2N2222A: Transistor, NPN; CCA: 133; MFG: FAIRCHILD; Part Number: MMBT2222A; RATING: 40V, 500mA; SOURCE: DIGI MMBT2222AFSCT-ND
R112 R137 R143 R157 R183 R638 R681 = R: Resistor; CCA: 176; ICA_MFR_NAME: PANASONIC; ICA_PARTNUM: $$1785048$$ERJ-3GSYJ102; MFG: VISHAY/DALE; Part Number: WSL0805R0100FEA; RATING: 1/8W; SOURCE: DIGI WSLA-.01CT-ND; TOLERANCE: 1%
R169 = R: Resistor; CCA: 51; MFG: VISHAY/DALE; Part Number: CRCW04023K24FKED; RATING: 1/16W; SOURCE: DIGI 541-3.24KLCT-ND; TOLERANCE: 1%
R181 = R: Resistor; CCA: 52; MFG: VISHAY/DALE; Part Number: CRCW040229K4FKED; RATING: 1/16W; SOURCE: DIGI 541-29.4KLCT-ND; TOLERANCE: 1%
R184 = R: Resistor; CCA: 163; MFG: VISHAY/DALE; Part Number: TNPW040210K2BEED; RATING: 1/16W; SOURCE: DIGI TNP10.2KDACT-ND; TOLERANCE: 0.1%
R2 R8 R9 R12 R22 R185 R720 = R: Resistor; CCA: 62; ICA_MFR_NAME: PANASONIC; ICA_PARTNUM: $$1785048$$ERJ-3GSYJ102; MFG: PANASONIC; Part Number: ERJ-2GE0R00X; RATING: 1/10W; SOURCE: DIGI P0.0JCT-ND
R647 = R: Resistor; CCA: 103; ICA_MFR_NAME: PANASONIC; ICA_PARTNUM: $$1785048$$ERJ-3GSYJ102; MFG: PANASONIC; Part Number: ERJ-L06KF10CV; RATING: 1/8W; SOURCE: DIGI P100LLCT-ND; TOLERANCE: 1%
R650 R677 = R: Resistor; CCA: 58; ICA_MFR_NAME: PANASONIC; ICA_PARTNUM: $$1785048$$ERJ-3GSYJ102; MFG: PANASONIC; Part Number: ERA-2AEB162X; RATING: 1/16W; SOURCE: DIGI P1.6KDCCT-ND; TOLERANCE: 0.1%
R651 R662 R678 = R: Resistor; CCA: 59; ICA_MFR_NAME: PANASONIC; ICA_PARTNUM: $$1785048$$ERJ-3GSYJ102; MFG: PANASONIC; Part Number: ERA-2AEB202X; RATING: 1/16W; SOURCE: DIGI P2.0KDCCT-ND; TOLERANCE: 0.1%
R663 = R: Resistor; CCA: 60; ICA_MFR_NAME: PANASONIC; ICA_PARTNUM: $$1785048$$ERJ-3GSYJ102; MFG: PANASONIC; Part Number: ERA-2AEB751X; RATING: 1/16W; SOURCE: DIGI P750DCCT-ND; TOLERANCE: 0.1%
R4 R6 R37 R118 R530 R534 R574 R625-R627 R629 R630 R633 R660 R723 R727 = R: Resistor; CCA: 65; ICA_MFR_NAME: PANASONIC; ICA_PARTNUM: $$1785048$$ERJ-3GSYJ102; MFG: PANASONIC; Part Number: ERJ-2GEJ103X; RATING: 1/10W; SOURCE: DIGI P10.0KLCT-ND; TOLERANCE: 5%
TP1-TP6 TP13 TP20 TP25 TP28 TP31 TP35 TP36 TP39 = Testpoint: Test point
TP21 = TP_LOOP: TP, Loop; MFG: Keystone; Part Number: 5011
U38 = TPS54331: IC, SW Regulator; CCA: 167; MFG: TI; Part Number: TPS54331D; SOURCE: MOUSER 595-TPS54331D
C503-C505 C507-C509 = CAP_NP: Capacitor; CCA: 13; MFG: AVX; Part Number: 08055C102KAT2A; RATING: 50V; SOURCE: DIGI 478-1371-1-ND; TOLERANCE: 10%; Type: X7R
C4 C6 C8 C510 C513 C556 C787 C792 C796 C961 C962 = CAP_NP: Capacitor; CCA: 34; MFG: KEMET; Part Number: C0402C104K8RACTU; RATING: 10V; SOURCE: DIGI 399-3520-1-ND; TOLERANCE: 10%; Type: X7R
DN1-DN8 = DS_DUAL_S_AJK_0: Diode, Schottky, Dual; CCA: 29; MFG: ON SEMI; RATING: 30V, 200mA; SOURCE: DIGI BAT54SWT1GOSCT-ND
J1 J2 = CON4: Connector, 4 pin, ribbon; CCA: 17; MFG: MOLEX; Part Number: 0528080470; SOURCE: MOUSER 538-52808-0470
L11 L19 = INDUCTOR: Inductor; CCA: 157; ICA_MFR_NAME: STEWARD; ICA_PARTNUM: $$731362$$MI0603J680R-10; MFG: BOURNS; Part Number: SRR1005-330Y; RATING: 1.2A; SOURCE: DIGI SRR1005-330Y-ND; TOLERANCE: 15%
R24-R26 R30-R32 = R: Resistor; CCA: 98; ICA_MFR_NAME: PANASONIC; ICA_PARTNUM: $$1785048$$ERJ-3GSYJ102; MFG: PANASONIC; Part Number: ERJ-6GEY0R00V; RATING: 1/8W; SOURCE: DIGI P0.0ACT-ND
R27-R29 R33-R35 = R: Resistor; CCA: 104; ICA_MFR_NAME: PANASONIC; ICA_PARTNUM: $$1785048$$ERJ-3GSYJ102; MFG: PANASONIC; Part Number: ERJ-P08J151V; RATING: 1/4W; SOURCE: DIGI P150ALCT-ND; TOLERANCE: 5%
R83 R117 = R: Resistor; CCA: 100; ICA_MFR_NAME: PANASONIC; ICA_PARTNUM: $$1785048$$ERJ-3GSYJ102; MFG: PANASONIC; Part Number: ERJ-8RQF2R2V; RATING: 1/4W; SOURCE: DIGI P2.2RCT-ND; TOLERANCE: 1%
R122 R135 R503-R505 R515-R517 R583 R628 R643 R653 R656 R664 = R: Resistor; CCA: 68; ICA_MFR_NAME: PANASONIC; ICA_PARTNUM: $$1785048$$ERJ-3GSYJ102; MFG: PANASONIC; Part Number: ERJ-2GEJ332X; RATING: 1/10W; SOURCE: DIGI P3.3KJCT-ND; TOLERANCE: 5%
D500-D505 = DIODE_SCHOTTKY: Diode, Schottky; CCA: 159; MFG: STMICRO; RATING: 60V, 500mA; SOURCE: DIGI 497-3787-1-ND
J4-J8 J15-J17 J20 J46 J47 = CON3: Connector, 3 pin; CCA: 19; MFG: MOLEX; Part Number: 0533980371; SOURCE: DIGI WM7607CT-ND
L1-L6 = INDUCTOR: Inductor; CCA: 57; ICA_MFR_NAME: STEWARD; ICA_PARTNUM: $$731362$$MI0603J680R-10; MFG: EPCOS - TDK; Part Number: B82462G4473M000; RATING: 750mA; SOURCE: DIGI PCD1378TR-ND; TOLERANCE: 20%
Q500 = FDN306P_2: MOSFET, P-Channel; CCA: 109; MFG: ON SEMI; SOURCE: DIGI FDN306PCT-ND
R5 = R: Resistor; CCA: 72; ICA_MFR_NAME: PANASONIC; ICA_PARTNUM: $$1785048$$ERJ-3GSYJ102; MFG: PANASONIC; Part Number: ERJ-2RKF1002X; RATING: 1/10W; SOURCE: DIGI P10.0KLCT-ND; TOLERANCE: 1%
R10 R11 = R: Resistor; CCA: 99; ICA_MFR_NAME: PANASONIC; ICA_PARTNUM: $$1785048$$ERJ-3GSYJ102; MFG: PANASONIC; Part Number: ERJ-6GEYJ111V; RATING: 1/8W; SOURCE: DIGI P110ACT-ND; TOLERANCE: 5%
R13 R17 = R: Resistor; CCA: 66; ICA_MFR_NAME: PANASONIC; ICA_PARTNUM: $$1785048$$ERJ-3GSYJ102; MFG: PANASONIC; Part Number: ERJ-2GEJ104X; RATING: 1/10W; SOURCE: DIGI P100KJCT-ND; TOLERANCE: 5%
R15 R18 = R: Resistor; CCA: 96; ICA_MFR_NAME: PANASONIC; ICA_PARTNUM: $$1785048$$ERJ-3GSYJ102; MFG: PANASONIC; Part Number: ERJ-3GEYJ222V; RATING: 1/10W; SOURCE: DIGI P2.2KGCT-ND; TOLERANCE: 5%
R500-R502 R512-R514 = R: Resistor; CCA: 105; DNI: DNI; ICA_MFR_NAME: PANASONIC; ICA_PARTNUM: $$1785048$$ERJ-3GSYJ102; MFG: PANASONIC; Part Number: ERJ-P14J680U; RATING: 1/2W; SOURCE: DIGI P68ASCT-ND; TOLERANCE: 5%
R506-R508 R521-R523 = R: Resistor; CCA: 102; DNI: DNI; ICA_MFR_NAME: PANASONIC; ICA_PARTNUM: $$1785048$$ERJ-3GSYJ102; MFG: PANASONIC; Part Number: ERJ-14YJ2R4U; RATING: 1/2W; SOURCE: DIGI P2.4VTR-ND; TOLERANCE: 5%
R741 R743 = R: Resistor; ICA_MFR_NAME: PANASONIC; ICA_PARTNUM: $$1785048$$ERJ-3GSYJ102; MFG: PANASONIC; Part Number: ERJ-3EKF75R0V; RATING: 1/10W; SOURCE: DIGI P75.0HCT-ND; TOLERANCE: 1%
R20 R21 R36 R50-R53 R127 R133 R637 R654 R657 R742 = R: Resistor; CCA: 64; ICA_MFR_NAME: PANASONIC; ICA_PARTNUM: $$1785048$$ERJ-3GSYJ102; MFG: PANASONIC; Part Number: ERJ-2GEJ102X; RATING: 1/10W; SOURCE: DIGI P1.0KJCT-ND; TOLERANCE: 5%
U6 = OPAMP_DUAL_0: IC, Comparator; CCA: 127; MFG: TI; Part Number: LM393APWR; SOURCE: DIGI 296-6610-1-ND
U500 = EEPROM: IC, EEPROM, Serial; CCA: 25; MFG: ATMEL; Part Number: AT24C32D-SSHM-B; RATING: 32K; SOURCE: DIGI AT24C32D-TH-B-ND
U2 U3 U509 U510 = 74LVC1G125_0: IC, Non-Inverting Buffer, Tri-State; CCA: 149; MFG: TI; Part Number: SN74LVC1G125DBVR; SOURCE: DIGI 296-11603-1-ND
VR1 VR2 = POT_R_S_1: IC, Potentiometer; CCA: 6; MFG: BOURNS; Part Number: 3314G-1-203E; RATING: 1/4W; SOURCE: DIGI 3314G-203ETR-ND; TOLERANCE: 20%
C7 = CAP_NP: Capacitor; CCA: 35; MFG: KEMET; Part Number: C0603C101J5GACTU; RATING: 50V; SOURCE: DIGI 399-1061-2-ND; TOLERANCE: 5%; Type: NP0
J3 J37 = CON6: Connector, 6 pin; CCA: 21; MFG: MOLEX; Part Number: 0533980671; SOURCE: DIGI WM7610CT-ND
J10 J12 J13 = CONN_4: Connector, 4 pin; CCA: 20; MFG: MOLEX; Part Number: 0533980471; SOURCE: DIGI WM7608CT-ND
J14 J28 = JUMPER-1x3: Jumper, 1x3; CCA: 129; MFG: HARWIN; Part Number: M22-2510305; SOURCE: DIGI 952-1312-ND
J31 = HDR_0: Jumper, 1x2; CCA: 128; MFG: HARWIN; Part Number: M22-2510205; SOURCE: DIGI 952-1311-ND
R1 R3 R7 R19 = R: Resistor; CCA: 62; DNI: DNI; ICA_MFR_NAME: PANASONIC; ICA_PARTNUM: $$1785048$$ERJ-3GSYJ102; MFG: PANASONIC; Part Number: ERJ-2GE0R00X; RATING: 1/10W; SOURCE: DIGI P0.0JCT-ND
R14 = R: Resistor; CCA: 74; ICA_MFR_NAME: PANASONIC; ICA_PARTNUM: $$1785048$$ERJ-3GSYJ102; MFG: PANASONIC; Part Number: ERJ-2RKF6491X; RATING: 1/10W; SOURCE: DIGI P6.49KLCT-ND; TOLERANCE: 1%
R38 R631 = R: Resistor; CCA: 64; DNI: DNI; ICA_MFR_NAME: PANASONIC; ICA_PARTNUM: $$1785048$$ERJ-3GSYJ102; MFG: PANASONIC; Part Number: ERJ-2GEJ102X; RATING: 1/10W; SOURCE: DIGI P1.0KJCT-ND; TOLERANCE: 5%
R40 = R: Resistor; CCA: 86; ICA_MFR_NAME: PANASONIC; ICA_PARTNUM: $$1785048$$ERJ-3GSYJ102; MFG: PANASONIC; Part Number: ERJ-3EKF4021V; RATING: 1/10W; SOURCE: DIGI P4.02KHCT-ND; TOLERANCE: 1%
R132 R160 R644 R645 R655 R685 = R: Resistor; CCA: 67; ICA_MFR_NAME: PANASONIC; ICA_PARTNUM: $$1785048$$ERJ-3GSYJ102; MFG: PANASONIC; Part Number: ERJ-2GEJ330X; RATING: 1/10W; SOURCE: DIGI P33JCT-ND; TOLERANCE: 5%
U4 = 74LVC1G17_0: IC, Non-Inverting Schmitt-Trigger Buffer; CCA: 148; MFG: TI; Part Number: SN74LVC1G17DBVR; SOURCE: DIGI 296-11933-1-ND
J27 = CON20A: Connector, 20 pin; CCA: 24; MFG: TE; Part Number: 5103308-5; SOURCE: DIGI A33165-ND
J29 = HDR_2: Jumper, 1x2; CCA: 128; MFG: HARWIN; Part Number: M22-2510205; SOURCE: DIGI 952-1311-ND
J52 J53 = CONN10: Conn 10 pin; MFG: Samtec; Part Number: TSM-110-01-S-SV
R119 = R: Resistor; CCA: 63; ICA_MFR_NAME: PANASONIC; ICA_PARTNUM: $$1785048$$ERJ-3GSYJ102; MFG: PANASONIC; Part Number: ERJ-2GEJ101X; RATING: 1/10W; SOURCE: DIGI P100JCT-ND; TOLERANCE: 5%
R684 = R: Resistor; CCA: 69; ICA_MFR_NAME: PANASONIC; ICA_PARTNUM: $$1785048$$ERJ-3GSYJ102; MFG: PANASONIC; Part Number: ERJ-2GEJ472X; RATING: 1/10W; SOURCE: DIGI P4.7KJCT-ND; TOLERANCE: 5%
RN1 RN2 = RESISTOR_DIP_8: Resistor Pack; CCA: 107; DNI: DNI; MFG: PANASONIC; Part Number: EXB-2HV330JV; RATING: 1/16W; SOURCE: DIGI Y1330CT-ND; TOLERANCE: 5%
RN500 RN501 = RESISTOR_DIP_8: Resistor Pack; CCA: 107; MFG: PANASONIC; Part Number: EXB-2HV330JV; RATING: 1/16W; SOURCE: DIGI Y1330CT-ND; TOLERANCE: 5%
SW1 = SW_SPST_1: Switch; CCA: 122; MFG: C&K COMPONENTS; Part Number: GT12MSCBE; SOURCE: DIGI CKN9050TR-ND
U22 = 74AHC1G125_0: IC, Non-Inverting Buffer, Tri-State; CCA: 144; MFG: TI; Part Number: SN74AHC1G125DBVR; SOURCE: DIGI 296-8744-1-ND
U25 = TPS3838: IC, Supervisor; CCA: 164; MFG: TI; Part Number: TPS3838K33DBVT; SOURCE: DIGI 296-3349-2-ND
U26 = 74LVC1G07: IC, Non-Inverting Buffer, Open Drain; CCA: 147; MFG: TI; Part Number: SN74LVC1G07DBVR; SOURCE: DIGI 296-8485-1-ND
D22 = LED_GREEN_CLEAR_0603: LED; MFG Part Number: LTST-C191KRKT; Part Number: LTST-C191KRKT
PCB2-PCB8 = SNT-100-BK-G
R141 = R: Resistor; CCA: 95; ICA_MFR_NAME: PANASONIC; ICA_PARTNUM: $$1785048$$ERJ-3GSYJ102; MFG: PANASONIC; Part Number: ERJ-3GEYJ221V; RATING: 1/10W; SOURCE: DIGI P220GCT-ND; TOLERANCE: 5%

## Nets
GND: C1.1 C2.1 C4.1 C5.1 C6.1 C7.1 C8.1 C26.1 C27.1 C88.1 C98.1 C105.2 C106.2 C107.1 C111.1 C114.2 C115.2 C117.2 C500.1 C501.1 C502.1 C510.1 C511.1 C513.1 C516.1 C517.1 C518.1 C556.1 C779.1 C787.1 C788.1 C789.2 C792.1 C796.1 C797.1 C815.1 C816.1 C875.1 C880.1 C899.1 C945.2 C958.1 C961.1 C962.1 D12.2(A) D16.2(A) D18.2(A) D19.2(A) D20.2(A) D23.2(A) D500.2(A) D501.2(A) D502.2(A) D503.2(A) D504.2(A) D505.2(A) D507.2(A) DN1.1 DN2.1 DN3.1 DN4.1 DN5.1 DN6.1 DN7.1 DN8.1 J3.2 J4.3 J5.3 J6.3 J7.3 J8.3 J10.4 J12.4 J13.4 J15.3 J16.3 J17.3 J20.3 J27.4 J27.6 J27.8 J27.10 J27.12 J27.14 J27.16 J27.18 J27.20 J29.2 J31.2 J37.6 J46.3 J47.3 J52.1 J52.10 J53.1 J53.10 Q1.1(EMITTER) Q501.1(EMITTER) Q504.1(EMITTER) Q505.1(EMITTER) R36.2 R38.1 R83.2 R117.2 R119.1 R127.2 R169.2 R181.2 R633.1 R650.2 R654.2 R662.1 R677.1 R742.1 TP21.1(SIG) U2.1(~{OE}) U2.3(GND) U3.1(~{OE}) U3.3(GND) U4.1(~{OE}) U4.3(GND) U6.4(V-) U22.2(I) U22.3(GND) U25.1(CT) U25.2(GND) U26.1(~{OE}) U26.3(GND) U32.AC6(VPGM) U32.M25(HW_TEST_EN) U33.AC6(VPGM) U33.M25(HW_TEST_EN) U38.7(GND) U500.4(GND) U500.7(WP) U509.1(~{OE}) U509.3(GND) U510.1(~{OE}) U510.3(GND) VR1.1(A) VR2.1(A) ; also on sheet 2 5 6 7 8 9 10 11 12 13 20 21 22 23 24 25 26 27 28 30 31 32 33 35 36
P5V_M: J47.1 Q500.2(S) R1.1 R3.1 R19.1 R530.2 ; also on sheet 13 23 26 30
P5V_S: R112.1 TP20.1 ; also on sheet 9
P12V: C105.1 C106.1 C107.2 C795.2 C797.2 C815.2 C816.2 C958.2 DN1.2 DN2.2 DN3.2 DN4.2 DN5.2 DN6.2 DN7.2 DN8.2 J46.1 R500.2 R501.2 R502.2 R512.2 R513.2 R514.2 R647.2 R723.2 U10.9(VBB3) U29.9(VBB3) U29.22(VBB1) U29.27(ISENK) U29.37(VBB2) U29.42(VBB4) U38.2(VIN) ; also on sheet 2 8 9 12 13 24 26 33
VDD1_INDEX_SENSE: C1.2 J5.1 R10.1
VDD2_INDEX_SENSE: C2.2 J4.1 R11.1
3D_TOGGLE: U33.E26(GPIO_53) U509.2(I) ; also on sheet 24
A1P8V2_SENSE: C788.2 R638.2 R651.1 TP25.1 U29.29(VLIN1)
A1P8V_S: R638.1 ; also on sheet 28
BLU_LED_EN: J14.1 ; also on sheet 24
CW_INDEX1: R13.1 R15.1 TP5.1 U6.1(OUT) ; also on sheet 12 25
CW_INDEX2: R17.1 R18.1 TP4.1 U6.7(OUT) U33.H25(GPIO_63)
CW_PWM1: R574.1 ; also on sheet 12
CW_PWM2: R660.1 U33.H26(GPIO_64)
CWCTR1: C507.1 C508.1 C509.1 DN8.3 J2.1 U10.13(CTAP)
CWCTR2: C503.1 C504.1 C505.1 DN4.3 J1.1 U29.13(CTAP)
CWY1A: DN5.3 J2.4 R30.2 R33.2
CWY1B: DN7.3 J2.3 R32.2 R35.2
CWY1C: DN6.3 J2.2 R31.2 R34.2
CWY2A: DN1.3 J1.4 R24.2 R27.2
CWY2B: DN3.3 J1.3 R26.2 R29.2
CWY2C: DN2.3 J1.2 R25.2 R28.2
DASYNC: U33.R22(GPIO_41) U33.T23(GPIO_40) ; also on sheet 25
DB/RED_PWM: R742.2 U33.B19(GPIO_04) U510.2(I) ; also on sheet 24
DMD_P3P3V: R183.2 ; also on sheet 11 36
DRV_RST: R656.1 U33.K22(GPIO_70) ; also on sheet 24
DYN_BLK_BUF: R741.2 U510.4(O)
EXT_ARSTZ: R534.1 ; also on sheet 2 12 33
FAN1_LOCKD: J8.2 R503.1 U33.B24(GPIO_18)
FAN1_SW: D500.1(C) L3.2 R506.1 ; also on sheet 12
FAN2_LOCKD: J7.2 R504.1 U33.D21(GPIO_19)
FAN2_SW: D501.1(C) L2.2 R507.1 ; also on sheet 12
FAN3_LOCKD: J6.2 R505.1 U33.C23(GPIO_20)
FAN3_SW: D502.1(C) L1.2 R508.1 ; also on sheet 12
FAN4_LOCKD: J17.2 R515.1 U33.H22(GPIO_60)
FAN4_SW: D503.1(C) L6.2 R521.1 ; also on sheet 12
FAN5_LOCKD: J16.2 R516.1 U33.H23(GPIO_61)
FAN5_SW: D504.1(C) L5.2 R522.1 ; also on sheet 12
FAN6_LOCKD: J15.2 R517.1 U33.J22(GPIO_65)
FAN6_SW: D505.1(C) L4.2 R523.1 ; also on sheet 12
GPIO_26: J14.2 U33.D24(GPIO_26)
GPIO_54: U33.F26(GPIO_54) ; also on sheet 24
GPIOX_INTZ: U33.E3(GPIO_82) ; also on sheet 35
GPIOX_RSTZ: U33.G22(GPIO_37) ; also on sheet 35
GRN_LED_EN: U33.C25(GPIO_25) ; also on sheet 24
HBT_CLK_OUT: R644.1 ; also on sheet 25
HBT_CLKIN_0: U33.U24(GPIO_44) ; also on sheet 25
HBT_DI_0: U33.U25(GPIO_43) ; also on sheet 25
HBT_DO: R645.1 ; also on sheet 25
HOLD_BOOTZ: J31.1 R657.2 U33.F24(GPIO_39) ; also on sheet 25
I2C_BUSY: U33.G24(GPIO_56) ; also on sheet 30
ICE_RSTZ: J27.15 R625.1 U25.4(\~{_RESE}T) U26.2(I)
ICTSEN: R654.1 U33.M24(ICTSEN)
INDEX1_SENSE_INPUT: J5.2 R5.1 U6.2(IN-)
INDEX2_SENSE_INPUT: J4.2 R6.1 U6.6(IN-)
IR0: U33.C26(GPIO_28) ; also on sheet 35
IR1: U33.E23(GPIO_29) ; also on sheet 35
LAMPLITZ: J3.1 R4.1 R14.1 ; also on sheet 24
LAMPLITZ_FLTR: C7.2 R4.2 TP1.1 U4.2(I)
LMP_TXD: J14.3 R37.1 R38.2 U3.2(I)
LMP_TXD_BUF: J3.5 R8.1
LMPCTRL: R36.1 R40.2 TP6.1 U2.2(I) U33.AC9(LMPCTRL) ; also on sheet 24
LMPCTRL_BUF: J3.6 R7.1
LMPCTRL_Z: J3.4 R9.1
LMPSTAT: U4.4(O) U33.AF8(LMPSTAT) ; also on sheet 25
MAN_RSTZ: J29.1 R118.1 SW1.3 U25.3(\~{_M}R)
MASTER: R133.1 U33.V26(GPIO_47)
OCLKA: U10.6(OSC) U29.6(OSC) ; also on sheet 12
OUT1A: R30.1 U10.12(OUTA)
OUT1A_SNUB: C509.2 R33.1
OUT1B: R32.1 U10.15(OUTB)
OUT1B_SNUB: C507.2 R35.1
OUT1C: R31.1 U10.16(OUTC)
OUT1C_SNUB: C508.2 R34.1
OUT2A: R24.1 U29.12(OUTA)
OUT2A_SNUB: C505.2 R27.1
OUT2B: R26.1 U29.15(OUTB)
OUT2B_SNUB: C503.2 R29.1
OUT2C: R25.1 U29.16(OUTC)
OUT2C_SNUB: C504.2 R28.1
P1P1V_S: C98.2 R137.2 R663.2 TP31.1 ; also on sheet 28
P1P8V_S: R681.1 TP35.1 ; also on sheet 28
P2P5V_S: Q503.2(D2) Q503.4(D4) R157.2 TP39.1
P3P3V_M: C5.2 C6.2 C510.2 C511.2 C513.2 C787.2 C792.2 C961.2 C962.2 J10.3 J12.3 J13.3 J27.1 J27.2 R2.1 R5.2 R6.2 R10.2 R11.2 R12.1 R14.2 R15.2 R18.2 R20.1 R21.1 R22.1 R37.2 R50.1 R51.1 R52.1 R53.1 R118.2 R122.2 R133.2 R135.2 R503.2 R504.2 R505.2 R515.2 R516.2 R517.2 R583.1 R625.2 R626.2 R627.2 R628.2 R629.2 R630.2 R631.2 R637.2 R643.2 R653.2 R656.2 R657.1 R684.2 R727.2 U4.5(VCC) U6.8(V+) U22.5(VCC) U25.5(VDD) U26.5(VCC) U500.3(A2) U500.8(VCC) U509.5(VCC) U510.5(VCC) VR1.3(B) VR2.3(B) ; also on sheet 12 13 20 21 23 24 27 30 35
P3P3V_S: D22.2(ANODE) R143.2 R664.1 TP36.1 ; also on sheet 12 22 25 26 28
PIPESTAT0R: RN2.3 U33.C6(ETM_PIPESTAT_0)
PIPESTAT1R: RN2.2 U33.B5(ETM_PIPESTAT_1)
PIPESTAT2R: RN2.1 U33.A4(ETM_PIPESTAT_2)
PMD1K2_CP1: C89.1 U29.18(CP1)
PMD1K2_CP2: C89.2 U29.17(CP2)
PMD1K2_FB_LIN1: R650.1 R651.2 U29.31(FB1)
PMD1K2_FB_P2P5V: C899.2 L21.2 R157.1 U29.46(V2P5)
PMD1K2_FB_P3P3V: C875.2 L20.2 R143.1 U29.45(V3P3)
PMD1K2_FB_P5V: C779.2 L16.1 R112.2 U29.24(V5)
PMD1K2_GD_CORE: Q6.1(G) U29.26(GDC)
PMD1K2_VCP: C795.1 U29.21(VCP)
PMD1K2_VREG: C789.1 U29.20(VREG) U29.47(TRIM)
PMD1K_FB_MOT1: C27.2 L11.1 U10.11(VM)
PMD1K_FB_MOT2: C88.2 L19.1 U29.11(VM)
PMD1K_GM_IN1: C556.2 R574.2 TP13.1 U10.8(GMIN)
PMD1K_GM_IN2: C796.2 R660.2 TP28.1 U29.8(GMIN)
PMD1K_SENSE_MOT1: R83.1 U10.14(SENSE)
PMD1K_SENSE_MOT2: R117.1 U29.14(SENSE)
PWRGOOD: U26.4(O) ; also on sheet 12 21 30
REAL_CWTACH1: R583.2 U10.5(TACH)
REAL_CWTACH2: R664.2 U29.5(TACH)
RED_LED_EN: U33.B26(GPIO_24) ; also on sheet 24
RTCK: J27.11 R160.1 R627.1
RTCKR: R160.2 U32.E4(RTCK)
S_GPIO_79: R141.1 U32.AE9(GPIO_79)
S_ICTSEN: R127.1 U32.M24(ICTSEN)
S_LLF_LED: D22.1(CATHODE) R141.2
S_PIPESTAT0R: RN1.3 U32.C6(ETM_PIPESTAT_0)
S_PIPESTAT1R: RN1.2 U32.B5(ETM_PIPESTAT_1)
S_PIPESTAT2R: RN1.1 U32.A4(ETM_PIPESTAT_2)
S_TDI: J28.2 U32.N25(TDI)
S_TDO1: J37.4 U32.N23(TDO1)
S_TDO2: J27.13 R626.1 U32.N22(TDO2)
S_TRACECLKR: RN1.5 U32.D7(ETM_TRACECLK)
S_TRACEPKT0R: RN500.8 U32.C2(TSTPT_0)
S_TRACEPKT1R: RN500.7 U32.D3(TSTPT_1)
S_TRACEPKT2R: RN500.6 U32.E6(TSTPT_2)
S_TRACEPKT3R: RN500.5 U32.D5(TSTPT_3)
S_TRACEPKT4R: RN500.4 U32.E7(TSTPT_4)
S_TRACEPKT5R: RN500.3 U32.C4(TSTPT_5)
S_TRACEPKT6R: RN500.2 U32.B4(TSTPT_6)
S_TRACEPKT7R: RN500.1 U32.E8(TSTPT_7)
S_TRACESYNCR: RN1.4 U32.A5(ETM_TRACESYNC)
SCL0: J13.1 R53.2 U33.A10(IIC0_SCL) ; also on sheet 30 35
SCL1: J10.1 R21.2 U33.D20(GPIO_14) U500.6(SCL) ; also on sheet 25 30 33 35
SCL2: J12.1 R51.2 U33.B22(GPIO_12) ; also on sheet 33
SDA0: J13.2 R52.2 U33.B10(IIC0_SDA) ; also on sheet 30 35
SDA1: J10.2 R20.2 U33.E19(GPIO_15) U500.5(SDA) ; also on sheet 25 30 33 35
SDA2: J12.2 R50.2 U33.C21(GPIO_13) ; also on sheet 33
SEQ_SYNC: R684.1 R685.1 U32.AB9(SEQ_SYNC)
SLAVE_INT: U33.V25(GPIO_48) ; also on sheet 25
SSP0_CSZ4: R132.2 U33.U26(GPIO_42)
SSP0_CSZ4_SLAVE: R122.1 R132.1 ; also on sheet 25
SSP0_CSZ5: R655.2 U33.J23(GPIO_66)
SSP0_CSZ5_DAD2: R643.1 R655.1 ; also on sheet 2
SSP2_CLK: U33.K23(GPIO_71) ; also on sheet 24
SSP2_CSZ_0: R135.1 U33.J26(GPIO_69) ; also on sheet 24
SSP2_DIN: R653.1 U33.K24(GPIO_72) ; also on sheet 24
SSP2_DO: U33.J25(GPIO_68) ; also on sheet 24
SW_BOOT: C113.1 U38.1(BOOT)
SW_COMP: C117.1 C118.1 U38.6(COMP)
SW_EN: R720.2 U38.3(EN)
SW_PH: C113.2 D23.1(C) L22.1 U38.8(PH)
SW_SS: C111.2 U38.4(SS)
SW_VOUT: C114.1 C115.1 L22.2 R183.1 R185.2
SW_VSNS: R169.1 R184.2 U38.5(VSNS)
SWNODE2_CORE: D507.1(C) L18.1 Q6.3(S) U29.25(LXC)
SWNODE2_P2P5V: D20.1(C) L21.1 U29.41(LX25)
SWNODE2_P3P3V: D19.1(C) L20.1 U29.43(LX33)
SWNODE2_P5V: D16.1(C) L16.2 U29.23(LX5)
SWNODE_MOT: D12.1(C) L11.2 U10.10(VMSW)
SWNODE_MOT2: D18.1(C) L19.2 U29.10(VMSW)
TCK: J27.9 J37.5 R628.1 U32.N24(TCK) U33.N24(TCK)
TDI: J27.5 J37.2 R630.1 U33.N25(TDI)
TDO1: J28.1 U33.N23(TDO1)
TDO2: J28.3 U33.N22(TDO2)
TMS1: J37.3 U32.P25(TMS1) U33.P25(TMS1)
TMS2: J27.7 R629.1 U32.P26(TMS2) U33.P26(TMS2)
TRACECLKR: RN2.5 U33.D7(ETM_TRACECLK)
TRACEPKT0R: RN501.8 U33.C2(TSTPT_0)
TRACEPKT1R: RN501.7 U33.D3(TSTPT_1)
TRACEPKT2R: RN501.6 U33.E6(TSTPT_2)
TRACEPKT3R: RN501.5 U33.D5(TSTPT_3)
TRACEPKT4R: RN501.4 U33.E7(TSTPT_4)
TRACEPKT5R: RN501.3 U33.C4(TSTPT_5)
TRACEPKT6R: RN501.2 U33.B4(TSTPT_6)
TRACEPKT7R: RN501.1 U33.E8(TSTPT_7)
TRACESYNCR: RN2.4 U33.A5(ETM_TRACESYNC)
TRSTZ: R637.1 U22.4(O) U32.M23(TRSTZ) U33.M23(TRSTZ)
TRSTZ_IN: J27.3 J37.1 R631.1 R633.2 U22.1(~{OE})
USB_ENZ: U33.E25(GPIO_38) ; also on sheet 20
N16836092: C500.2 J8.1 L3.1 R500.1 R506.2
N16836211: R13.2 TP2.1 U6.3(IN+) VR1.2(WIPER)
N16862598: J3.3 R3.2 R12.2
N16862628: Q1.2(BASE) R40.1
N16862652: R7.2 U2.4(O)
N16862691: R8.2 U3.4(O)
N16862716: C8.2 R19.2 R22.2 U3.5(VCC)
N16862889: C4.2 R1.2 R2.2 U2.5(VCC)
N16862891: Q1.3(COLLECTOR) R9.2
N16902443: R685.2 U33.AB9(SEQ_SYNC)
N17031378: C501.2 J7.1 L2.1 R501.1 R507.2
N17031778: C502.2 J6.1 L1.1 R502.1 R508.2
N17032456: C516.2 J17.1 L6.1 R512.1 R521.2
N17032580: C517.2 J16.1 L5.1 R513.1 R522.2
N17032754: C518.2 J15.1 L4.1 R514.1 R523.2
N17036356: R17.2 TP3.1 U6.5(IN+) VR2.2(WIPER)
N17038227: J46.2 R741.1
N17038557: J47.2 R743.1
N17038579: R743.2 U509.4(O)
N17059557: R662.2 R663.1 U29.30(/FBC)
N17059579: Q6.2(D2) Q6.4(D4) R647.1 U29.28(ISEN)
N17059583: D17.2(A) L18.2
N17059602: D17.1(K) R137.1
N17410797: C880.2 Q503.3(S) R678.2 R681.2
N17410821: Q503.1(G) U29.33(GD2)
N17410829: R677.2 R678.1 U29.32(FB2)
N17451899: R119.2 SW1.1
N17529082: Q501.2(BASE) R534.2
N17529223: Q500.1(G) Q501.3(COLLECTOR) R530.1
N17529899: C26.2 J20.1 Q500.3(D)
N18120972: R645.2 U33.V24(GPIO_49)
N18120994: R644.2 U33.V23(GPIO_50)
N18146702: C945.1 Q505.2(BASE) R727.1
N18146780: Q504.2(BASE) Q505.3(COLLECTOR) R723.1
N18146794: Q504.3(COLLECTOR) R720.1
N19674154: J52.2 RN501.16
N19674157: J52.3 RN501.15
N19674160: J52.4 RN501.14
N19674163: J52.5 RN501.13
N19674166: J52.6 RN501.12
N19674172: J52.7 RN501.11
N19674175: J52.8 RN501.10
N19674178: J52.9 RN501.9
N19675045: J53.3 RN500.15
N19675047: J53.2 RN500.16
N19675049: J53.8 RN500.10
N19675051: J53.7 RN500.11
N19675053: J53.6 RN500.12
N19675055: J53.5 RN500.13
N19675057: J53.4 RN500.14
N19675063: J53.9 RN500.9
N20811898: R184.1 R185.1
N20966976: C118.2 R181.1

Not connected (* = marked no-connect by the designer): J20 2*; J27 17* 19*; RN1 6* 7* 8* 9* 10* 11* 12* 13* 14* 15* 16*; RN2 6* 7* 8* 9* 10* 11* 12* 13* 14* 15* 16*; U32 A20(GPIO_07)* A21(GPIO_08)* A22(GPIO_10)* A23(GPIO_11)* AB10(GPIO_81)* AB11(GPIO_77)* AC10(GPIO_76)* AD9(GPIO_80)* AD10(GPIO_75)* AE10(GPIO_74)* AF10(GPIO_73)* B20(GPIO_05)* B21(GPIO_09)* C20(GPIO_06)* D22(GPIO_22)* D25(GPIO_30)* D26(GPIO_33)* E20(GPIO_21)* E21(GPIO_23)* E24(GPIO_32)* F22(GPIO_31)* F23(GPIO_34)* F25(GPIO_57)* G25(GPIO_58)*; U33 A19(GPIO_03)* AB12(GPIO_52)* AC11(GPIO_51)* C19(GPIO_00)* D19(GPIO_01)* E4(RTCK)* E18(GPIO_02)* G26(GPIO_59)* H24(GPIO_62)* J24(GPIO_67)* T22(GPIO_46)* U23(GPIO_45)*; U500 1(A0)* 2(A1)*

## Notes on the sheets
sheet 14
- 4
- NOTE:
  Consult the DLPA100 Data Sheet for
  external component specifications.
- NOTE:
  R587, R525, R46, R576, R14 are used
  for current measurement and are not required for
  production units.
- DPAK
- IMPORTANT NOTE:
  The PCB should be designed such that the
  specifications are not exceeded when the
  DLPC4420 is operated under the maximum current
  conditions specified in the DLPC4420 datasheet.
- 2
- 1
- 3
- 4
- DPAK
- 2
- 1
- 3
- Secondary DLPA100 Supplies
- (C) COPYRIGHT 2023
         Texas Instruments
        All Rights Reserved
sheet 15
- Note: If not using the motor driver on the
  DLPA100 follow these guidelines for unused pins:
  GMIN (pin 8) – Ground
  OSC (pin 6) – Ground
  SENSE (pin 14) – Ground
  CTAP (pin 13) – VBB
  VM (pin 11) – VBB
  OUTA (pin 12) – No Connect
  OUTB (pin 15) – No Connect
  OUTC (pin 16) – No Connect
  TACH (pin 5) – No Connect
  VMSW (pin 10) – No Connect
  VBB (pin 37) – VBB
- 3
- SOT-323
- 1
- 2
- CW1 MOTOR DRIVE
- NOTE: This resistor value is dependant upon the CW motor used.
   The value range is 0.47 ohms to 2.2 ohms.
   The target vlotage range for the SENSE pin is 100-150mV
   when the CW is running at a stable speed.
- CW2 MOTOR DRIVE
- NOTE: This resistor value is dependant upon the CW motor used.
   The value range is 0.47 ohms to 2.2 ohms.
   The target vlotage range for the SENSE pin is 100-150mV
   when the CW is running at a stable speed.
- Color Wheel Drive
- (C) COPYRIGHT 2023
         Texas Instruments
        All Rights Reserved
sheet 16
- 3D I/F
- FAN 1
- FAN 4
- DYNAMIC BLACK I/F
- FAN 2
- FAN 5
- 5V FAN
- 3
- FAN 3
- SOT-23
- FAN 6
- 2
- 1
- CW1 INDEX
  SENSOR
- Projector Settings Memory
  I2C Address set to 0xA8
- CW2 INDEX
  SENSOR
- Fan, Color Wheel Interface and Peripherals
- (C) COPYRIGHT 2023
         Texas Instruments
        All Rights Reserved
sheet 17
- J31 installed - Hold in Boot Loader
- Some ballast may require a different value of R14 for
  robust communication. Some ballast may require a value
  of 1.5k. See ballast data sheet for more information.
- Note: GPIO_25 can be used as LAMP_SYNC if needed
- BALLAST CONTROL
- Primary
- Primary ASIC GPIO, I2C, and Ballast Control
- (C) COPYRIGHT 2023
         Texas Instruments
        All Rights Reserved
sheet 18
- NOTE:
  TRSTZ should be pulled down
  for production designs.
- REALVIEW ICE
  JTAG I/F
- MANUAL RESET JUMPER
- INSTALLED
- HOLD IN RESET
- NOT INSTALLED
- NORMAL OPERATION (DEFAULT)
- JTAG BOUNDARY SCAN
- Primary
- Primary Controller Test Points, ARM Trace, JTAG, and Reset
- (C) COPYRIGHT 2023
         Texas Instruments
        All Rights Reserved
sheet 19
- Secondary
- Jumper Caps instances for EVM
- Secondary
- Secondary Controller Test Points, ARM Trace, and JTAG
- (C) COPYRIGHT 2023
         Texas Instruments
        All Rights Reserved
